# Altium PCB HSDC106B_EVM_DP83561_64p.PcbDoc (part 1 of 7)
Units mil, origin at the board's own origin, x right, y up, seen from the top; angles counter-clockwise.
Board outline 8750.24 x 6394.7 mil, 6 copper layers (Top Layer, GND1, SIG1, SIG2, GND2, Bottom Layer), stack 60.4 mil thick; 472 components, 324 nets, 1622 pads, 1086 vias.
Unrouted connection lines stored in the file: 1.
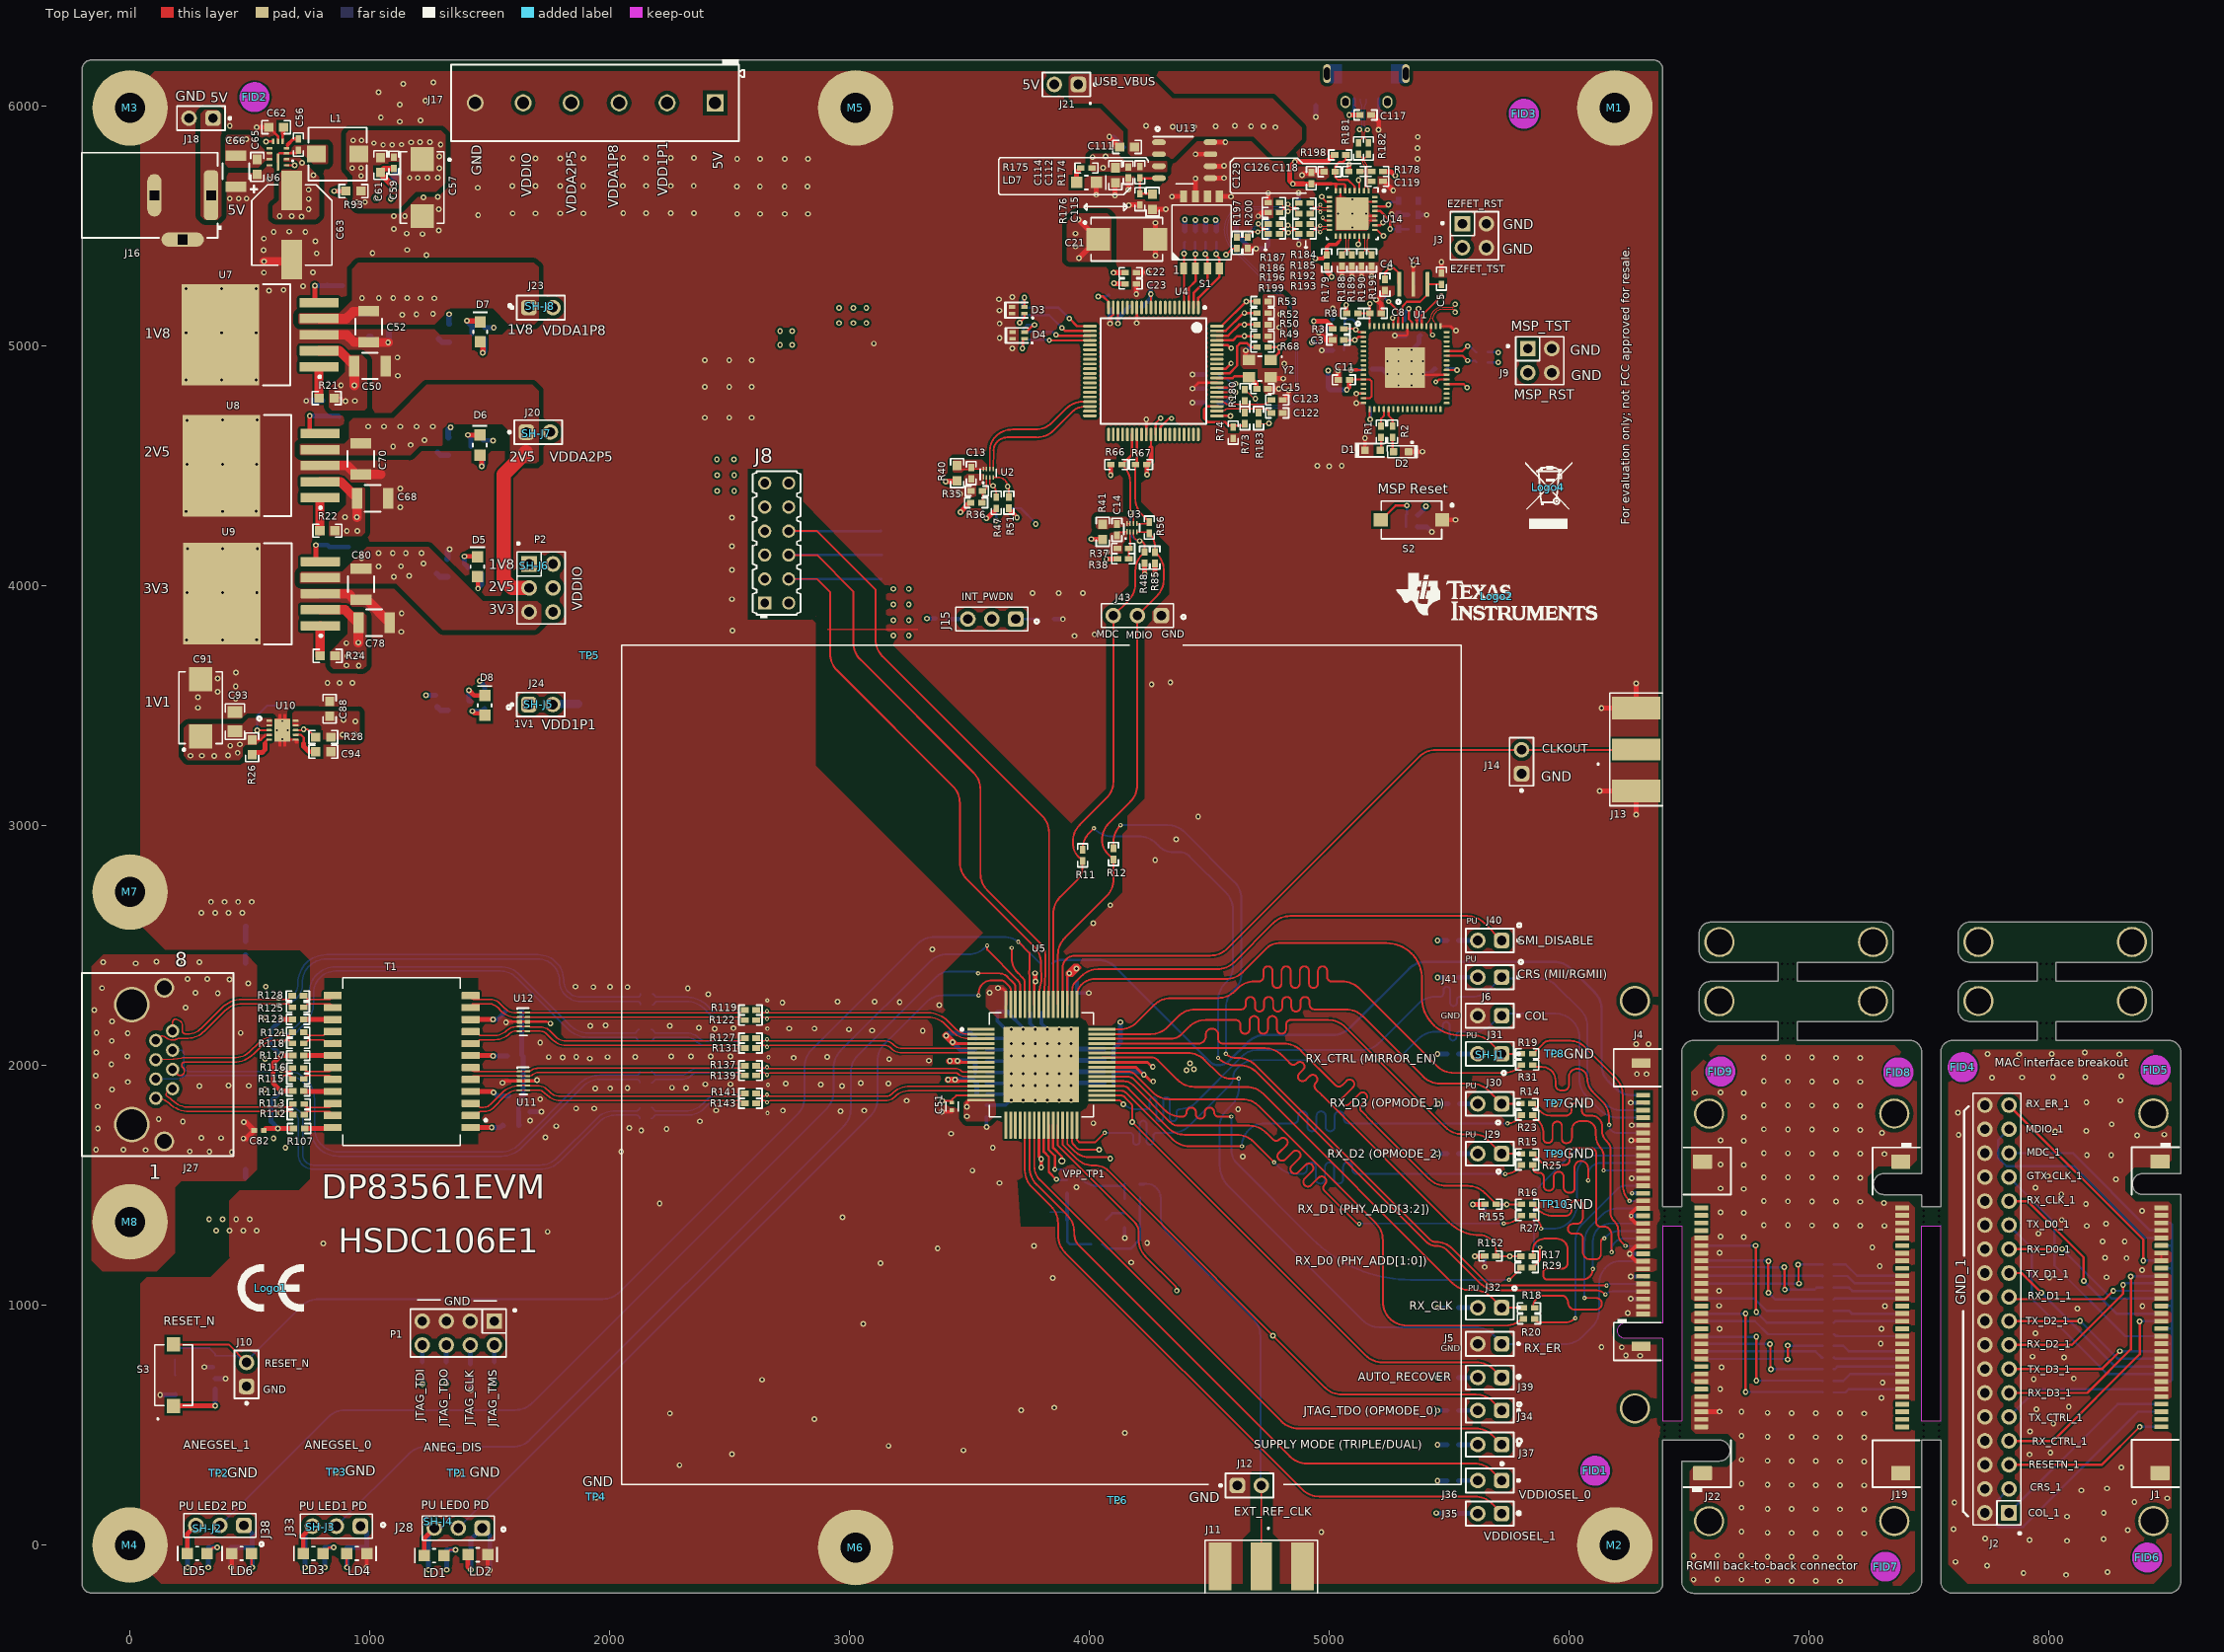
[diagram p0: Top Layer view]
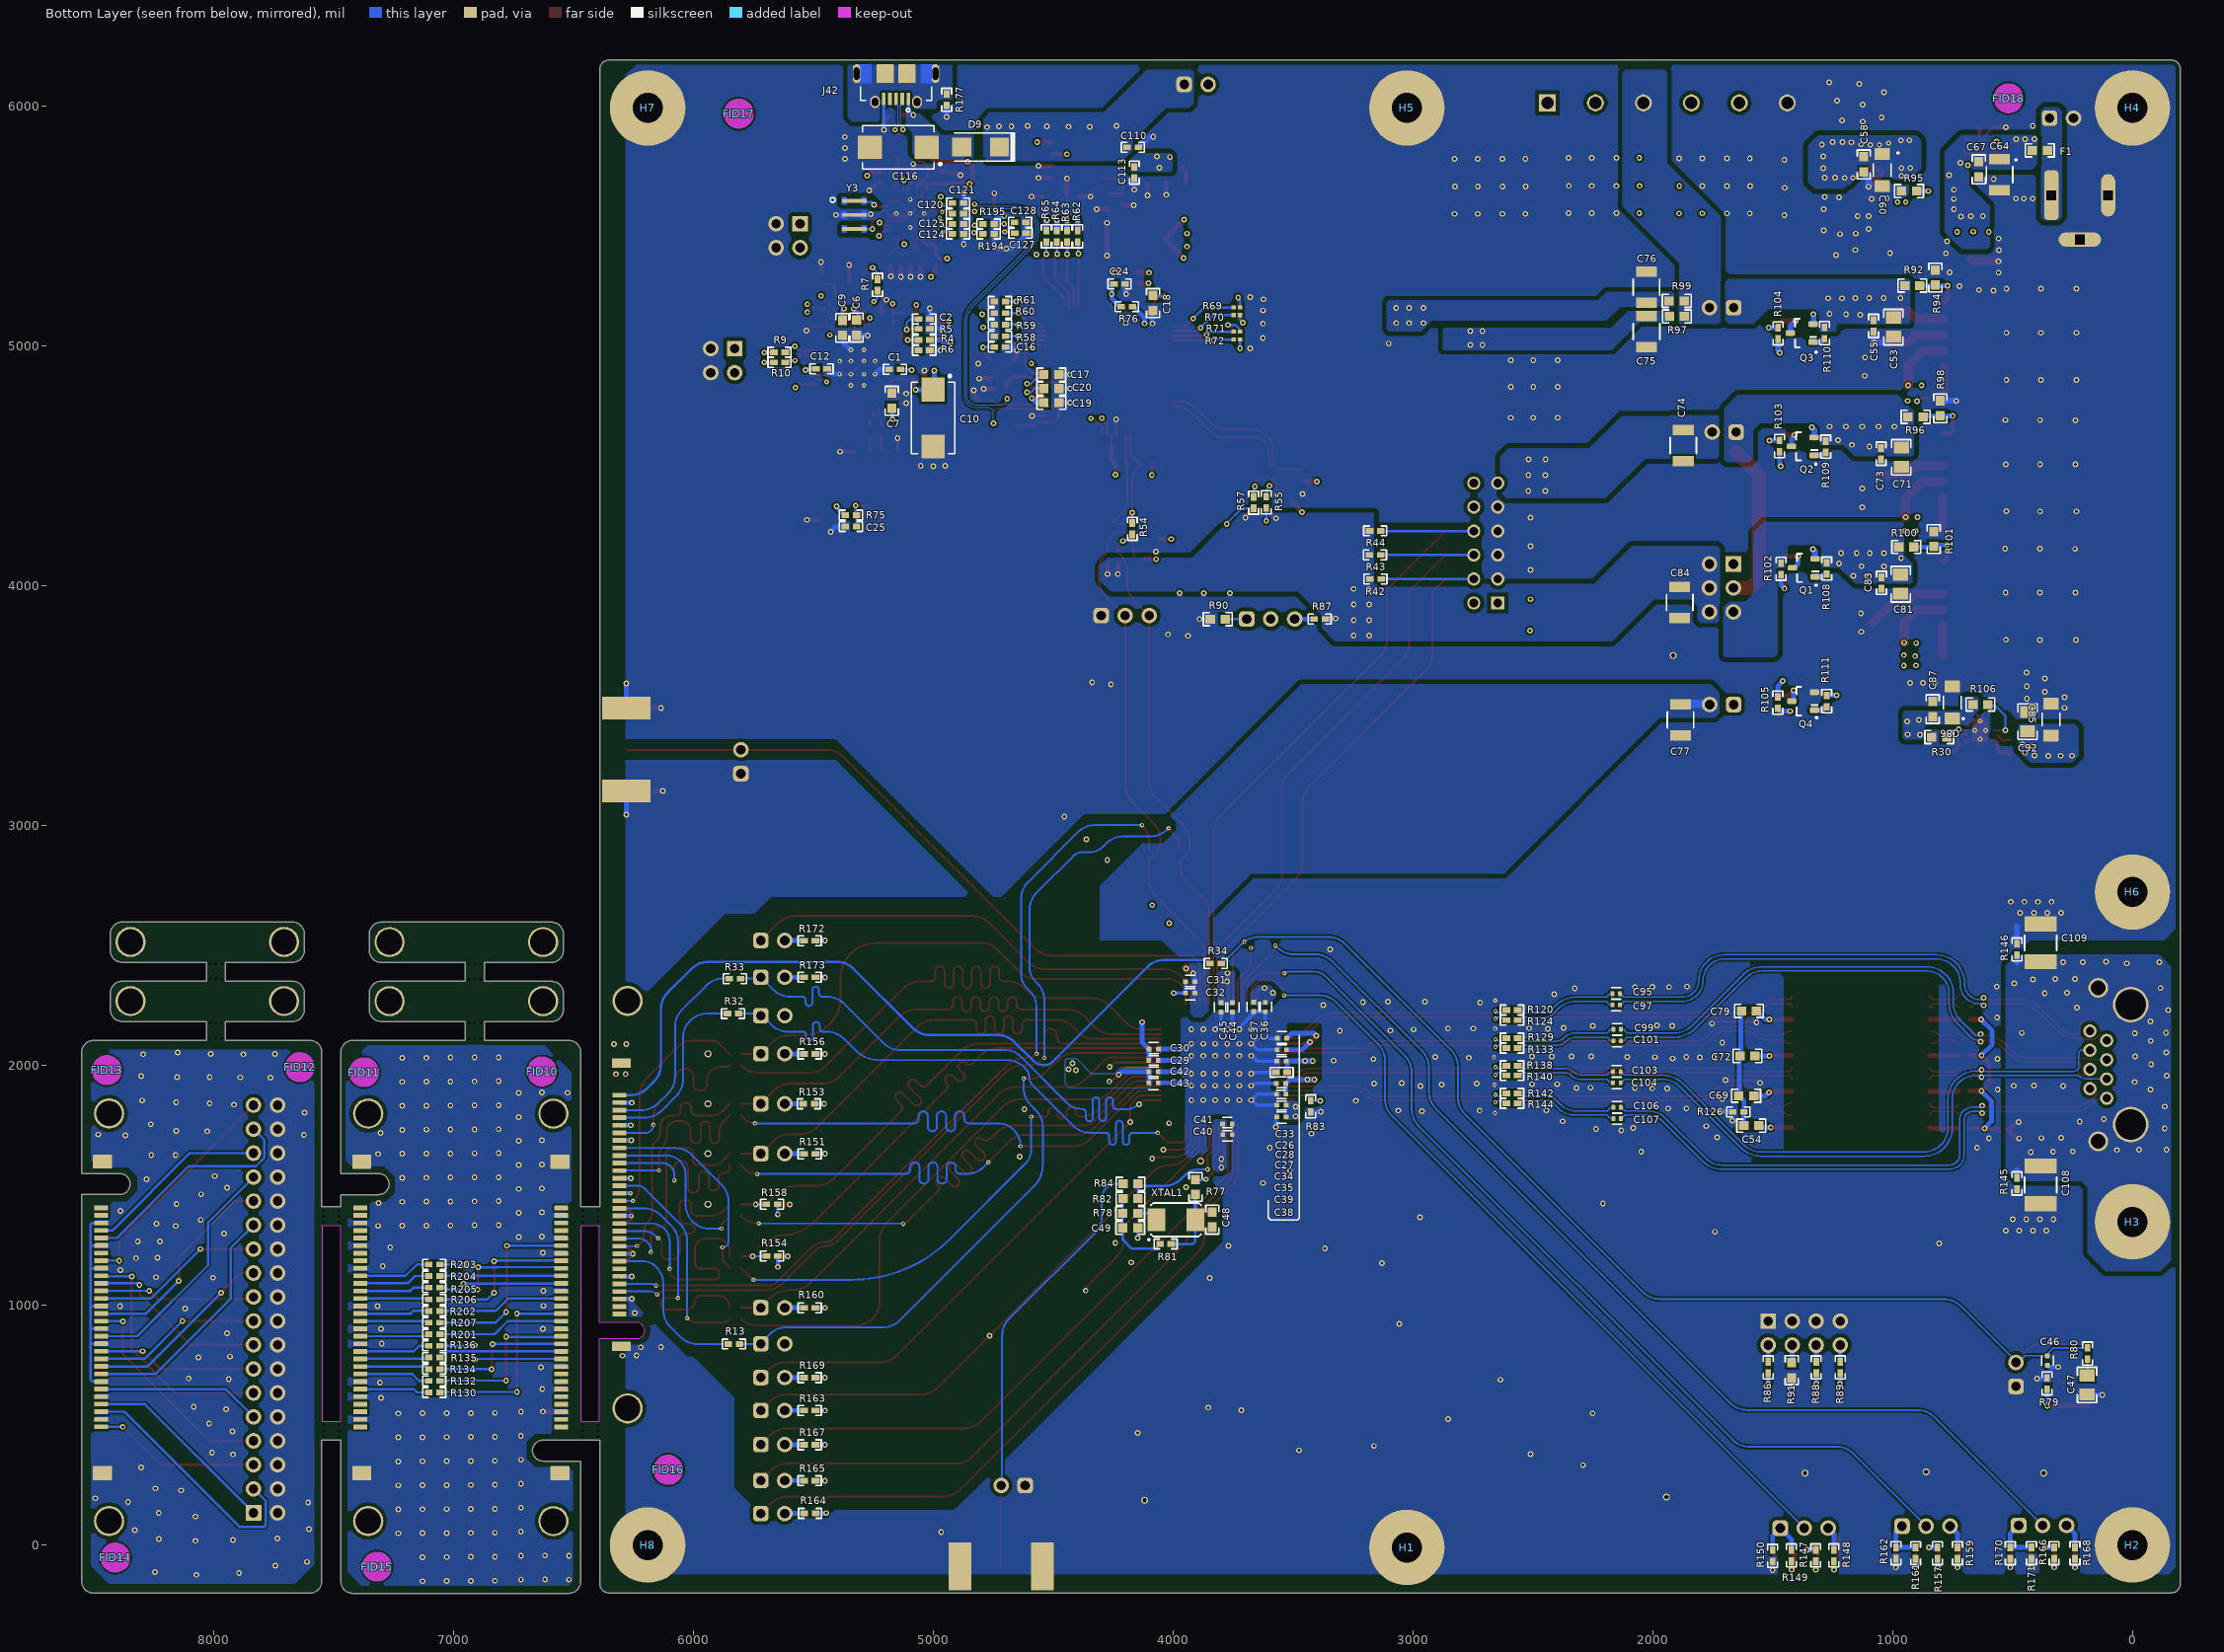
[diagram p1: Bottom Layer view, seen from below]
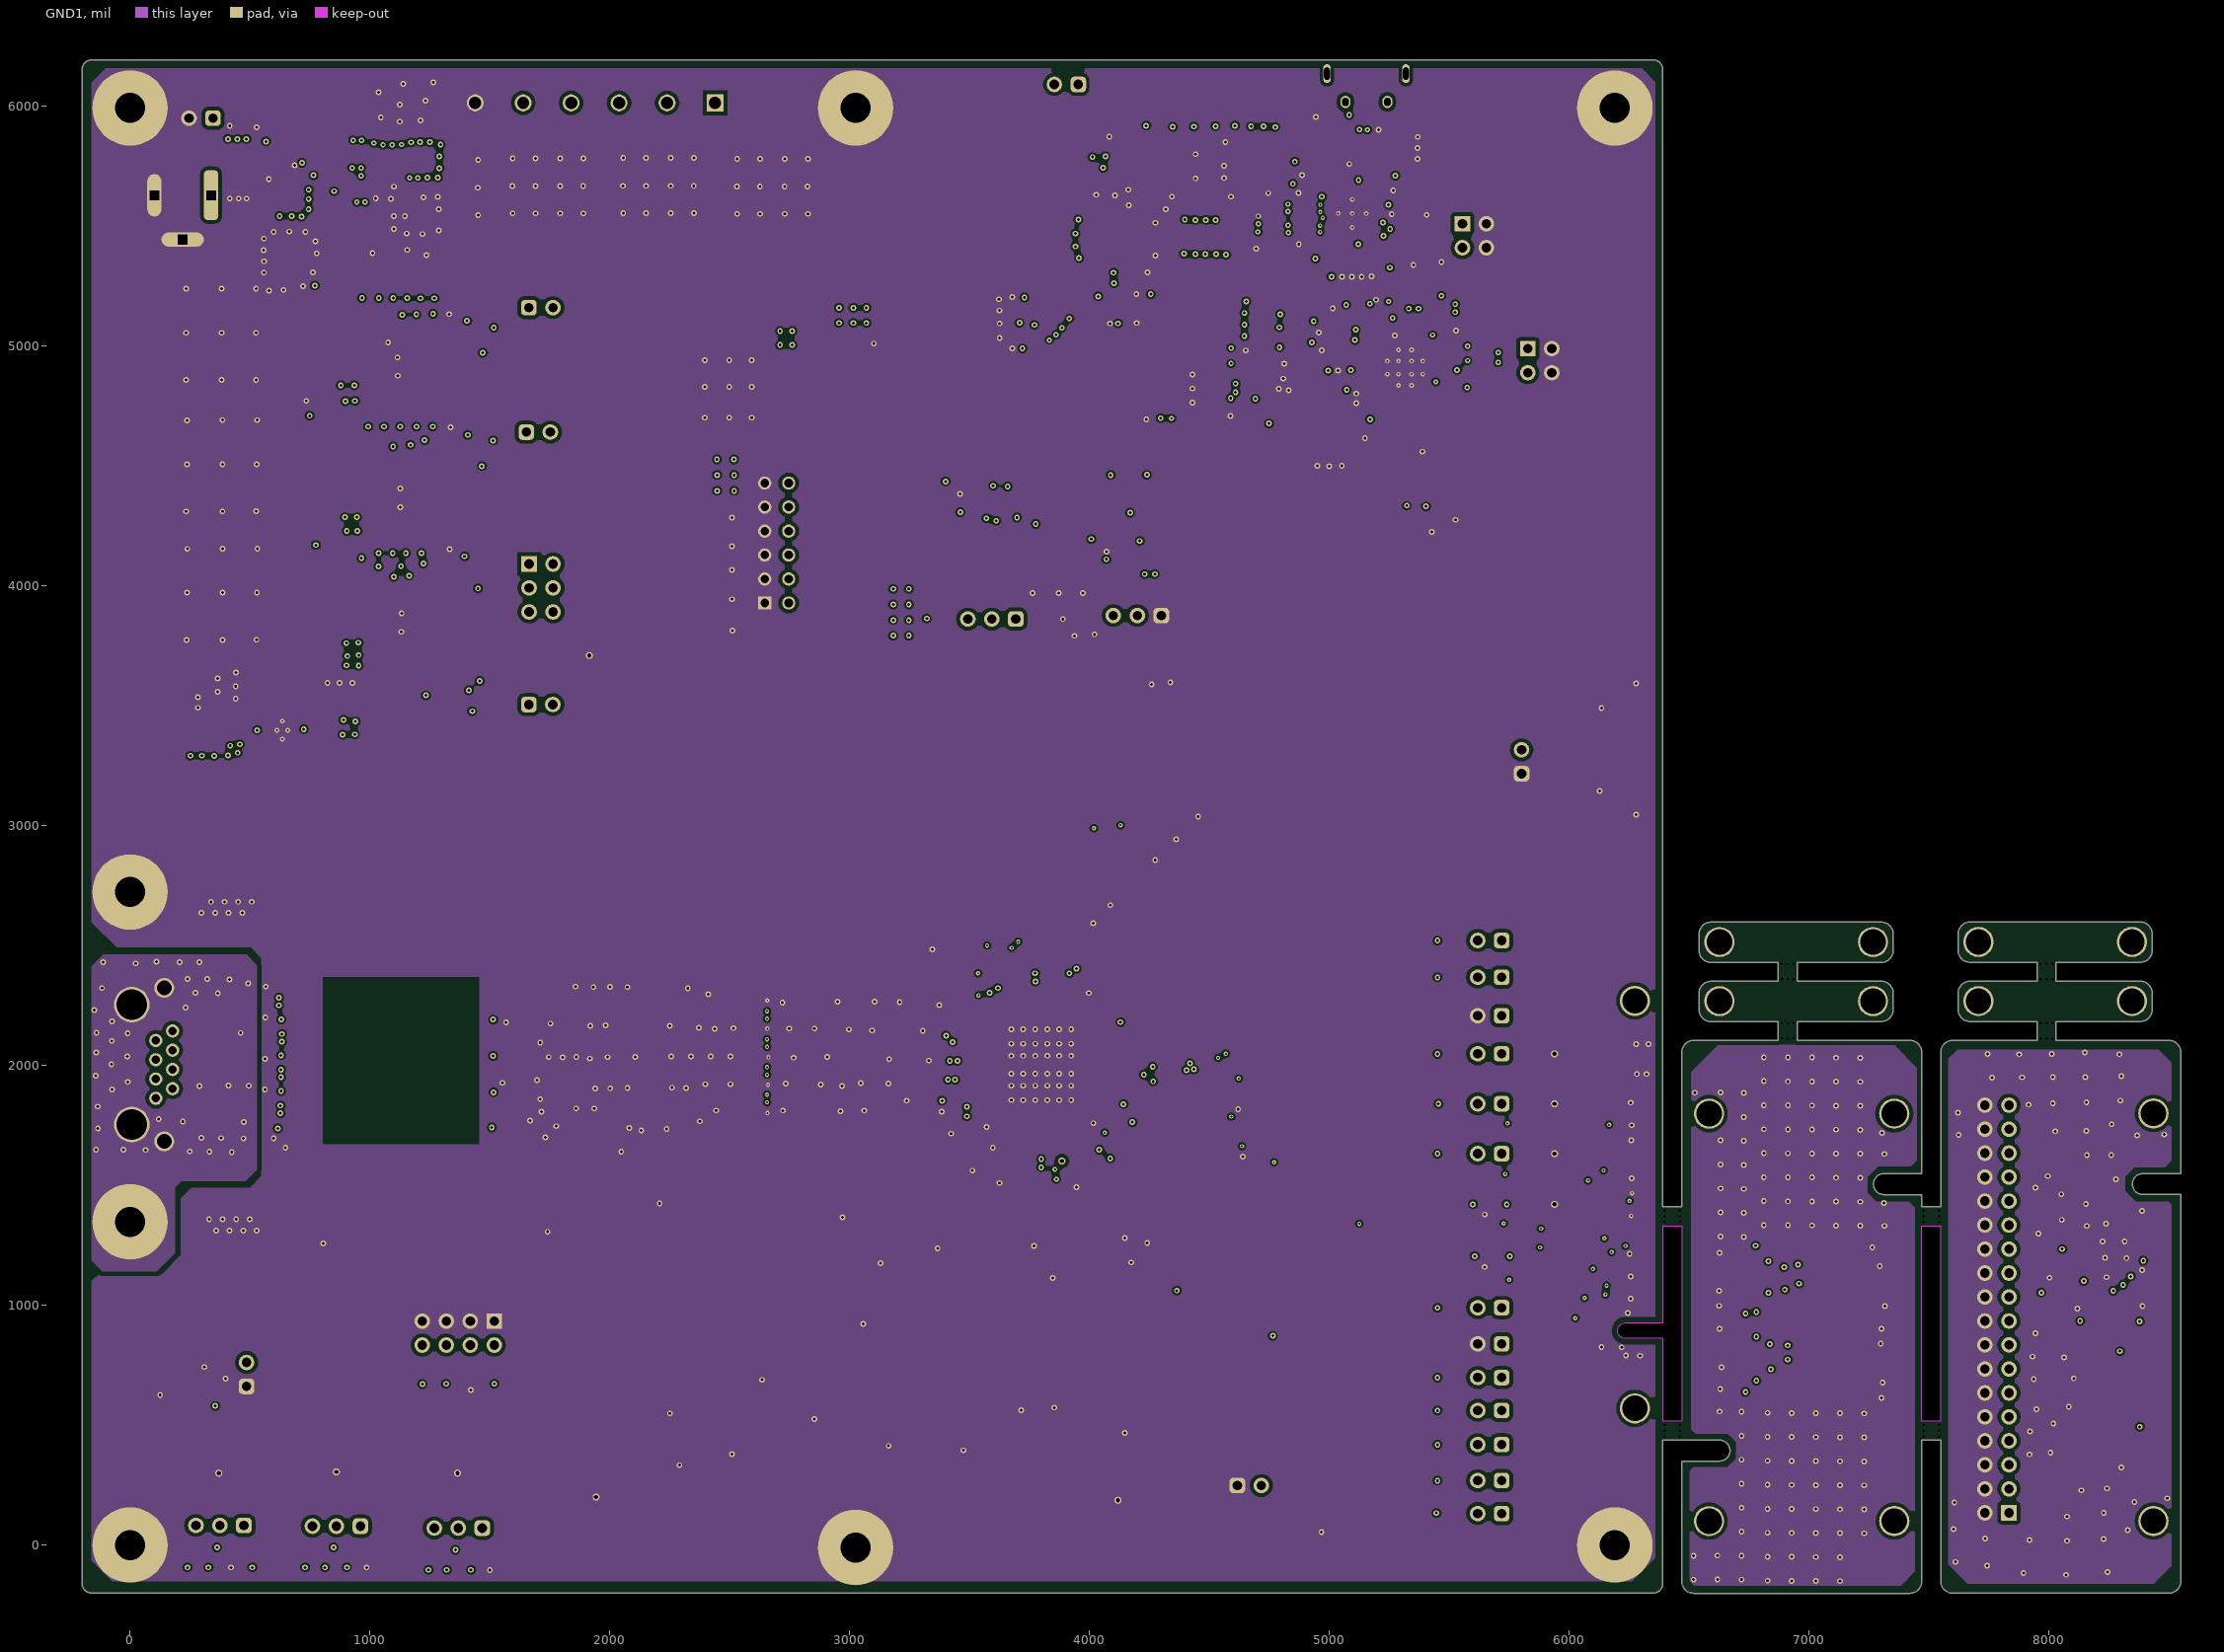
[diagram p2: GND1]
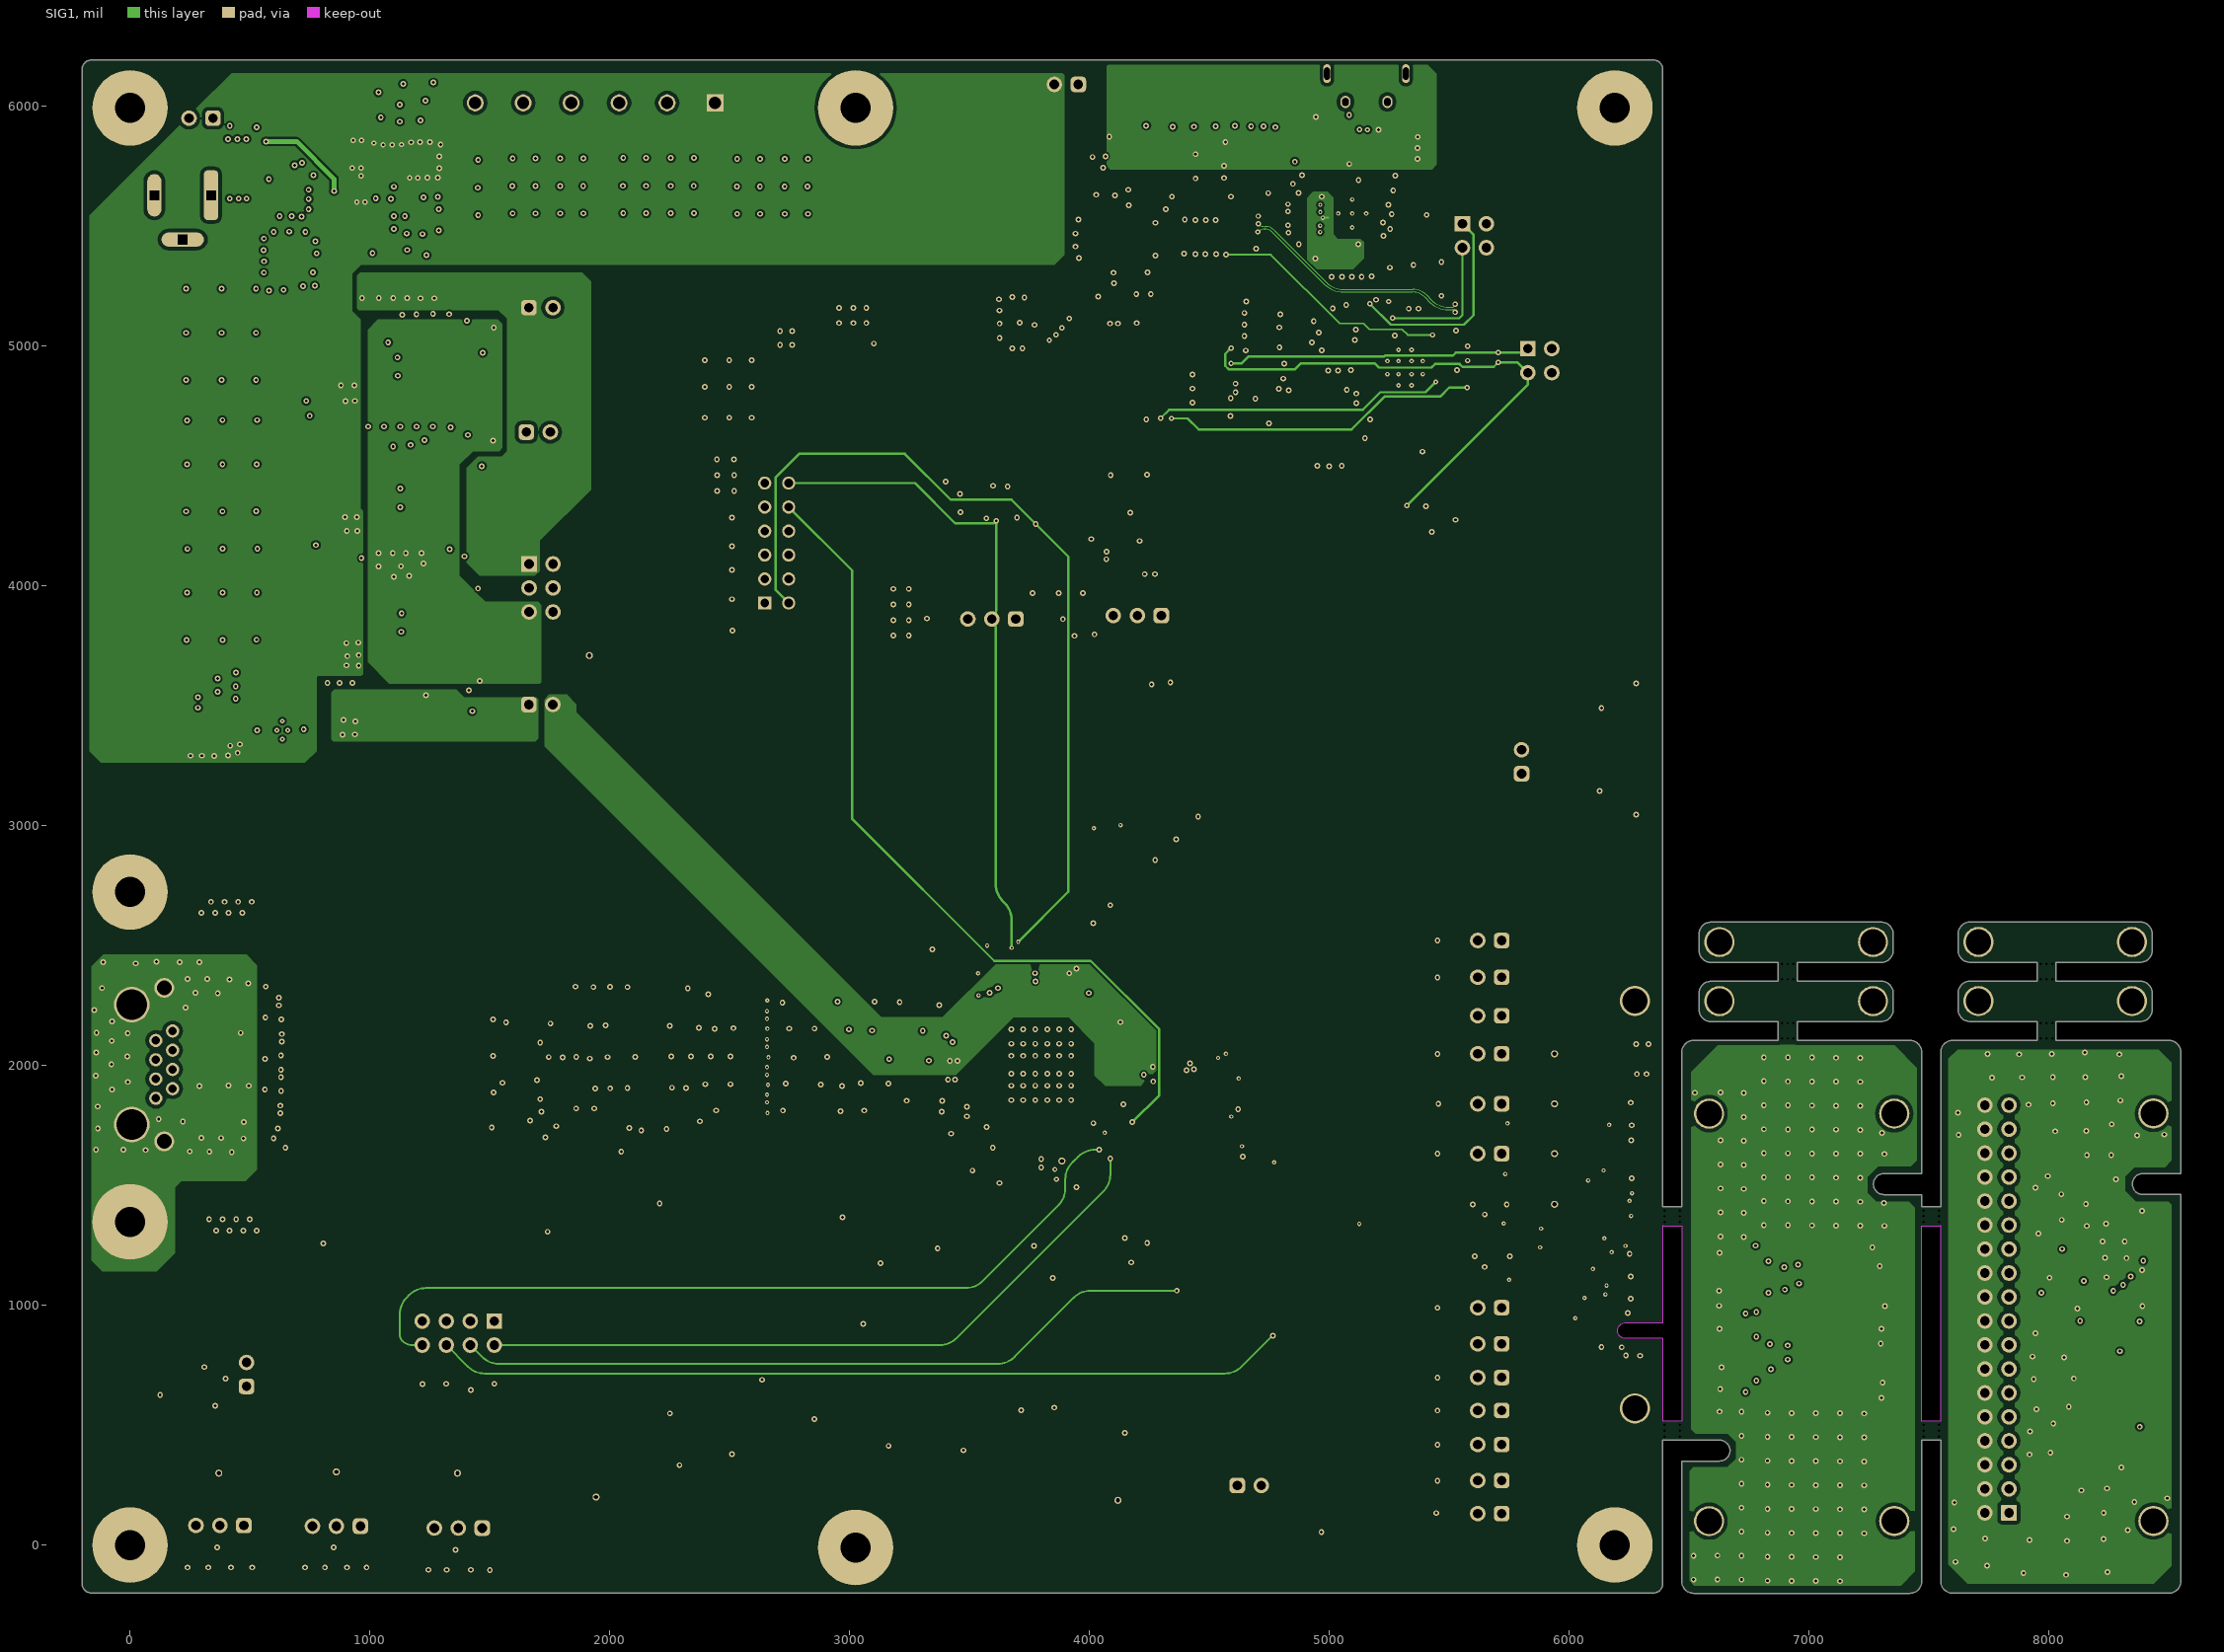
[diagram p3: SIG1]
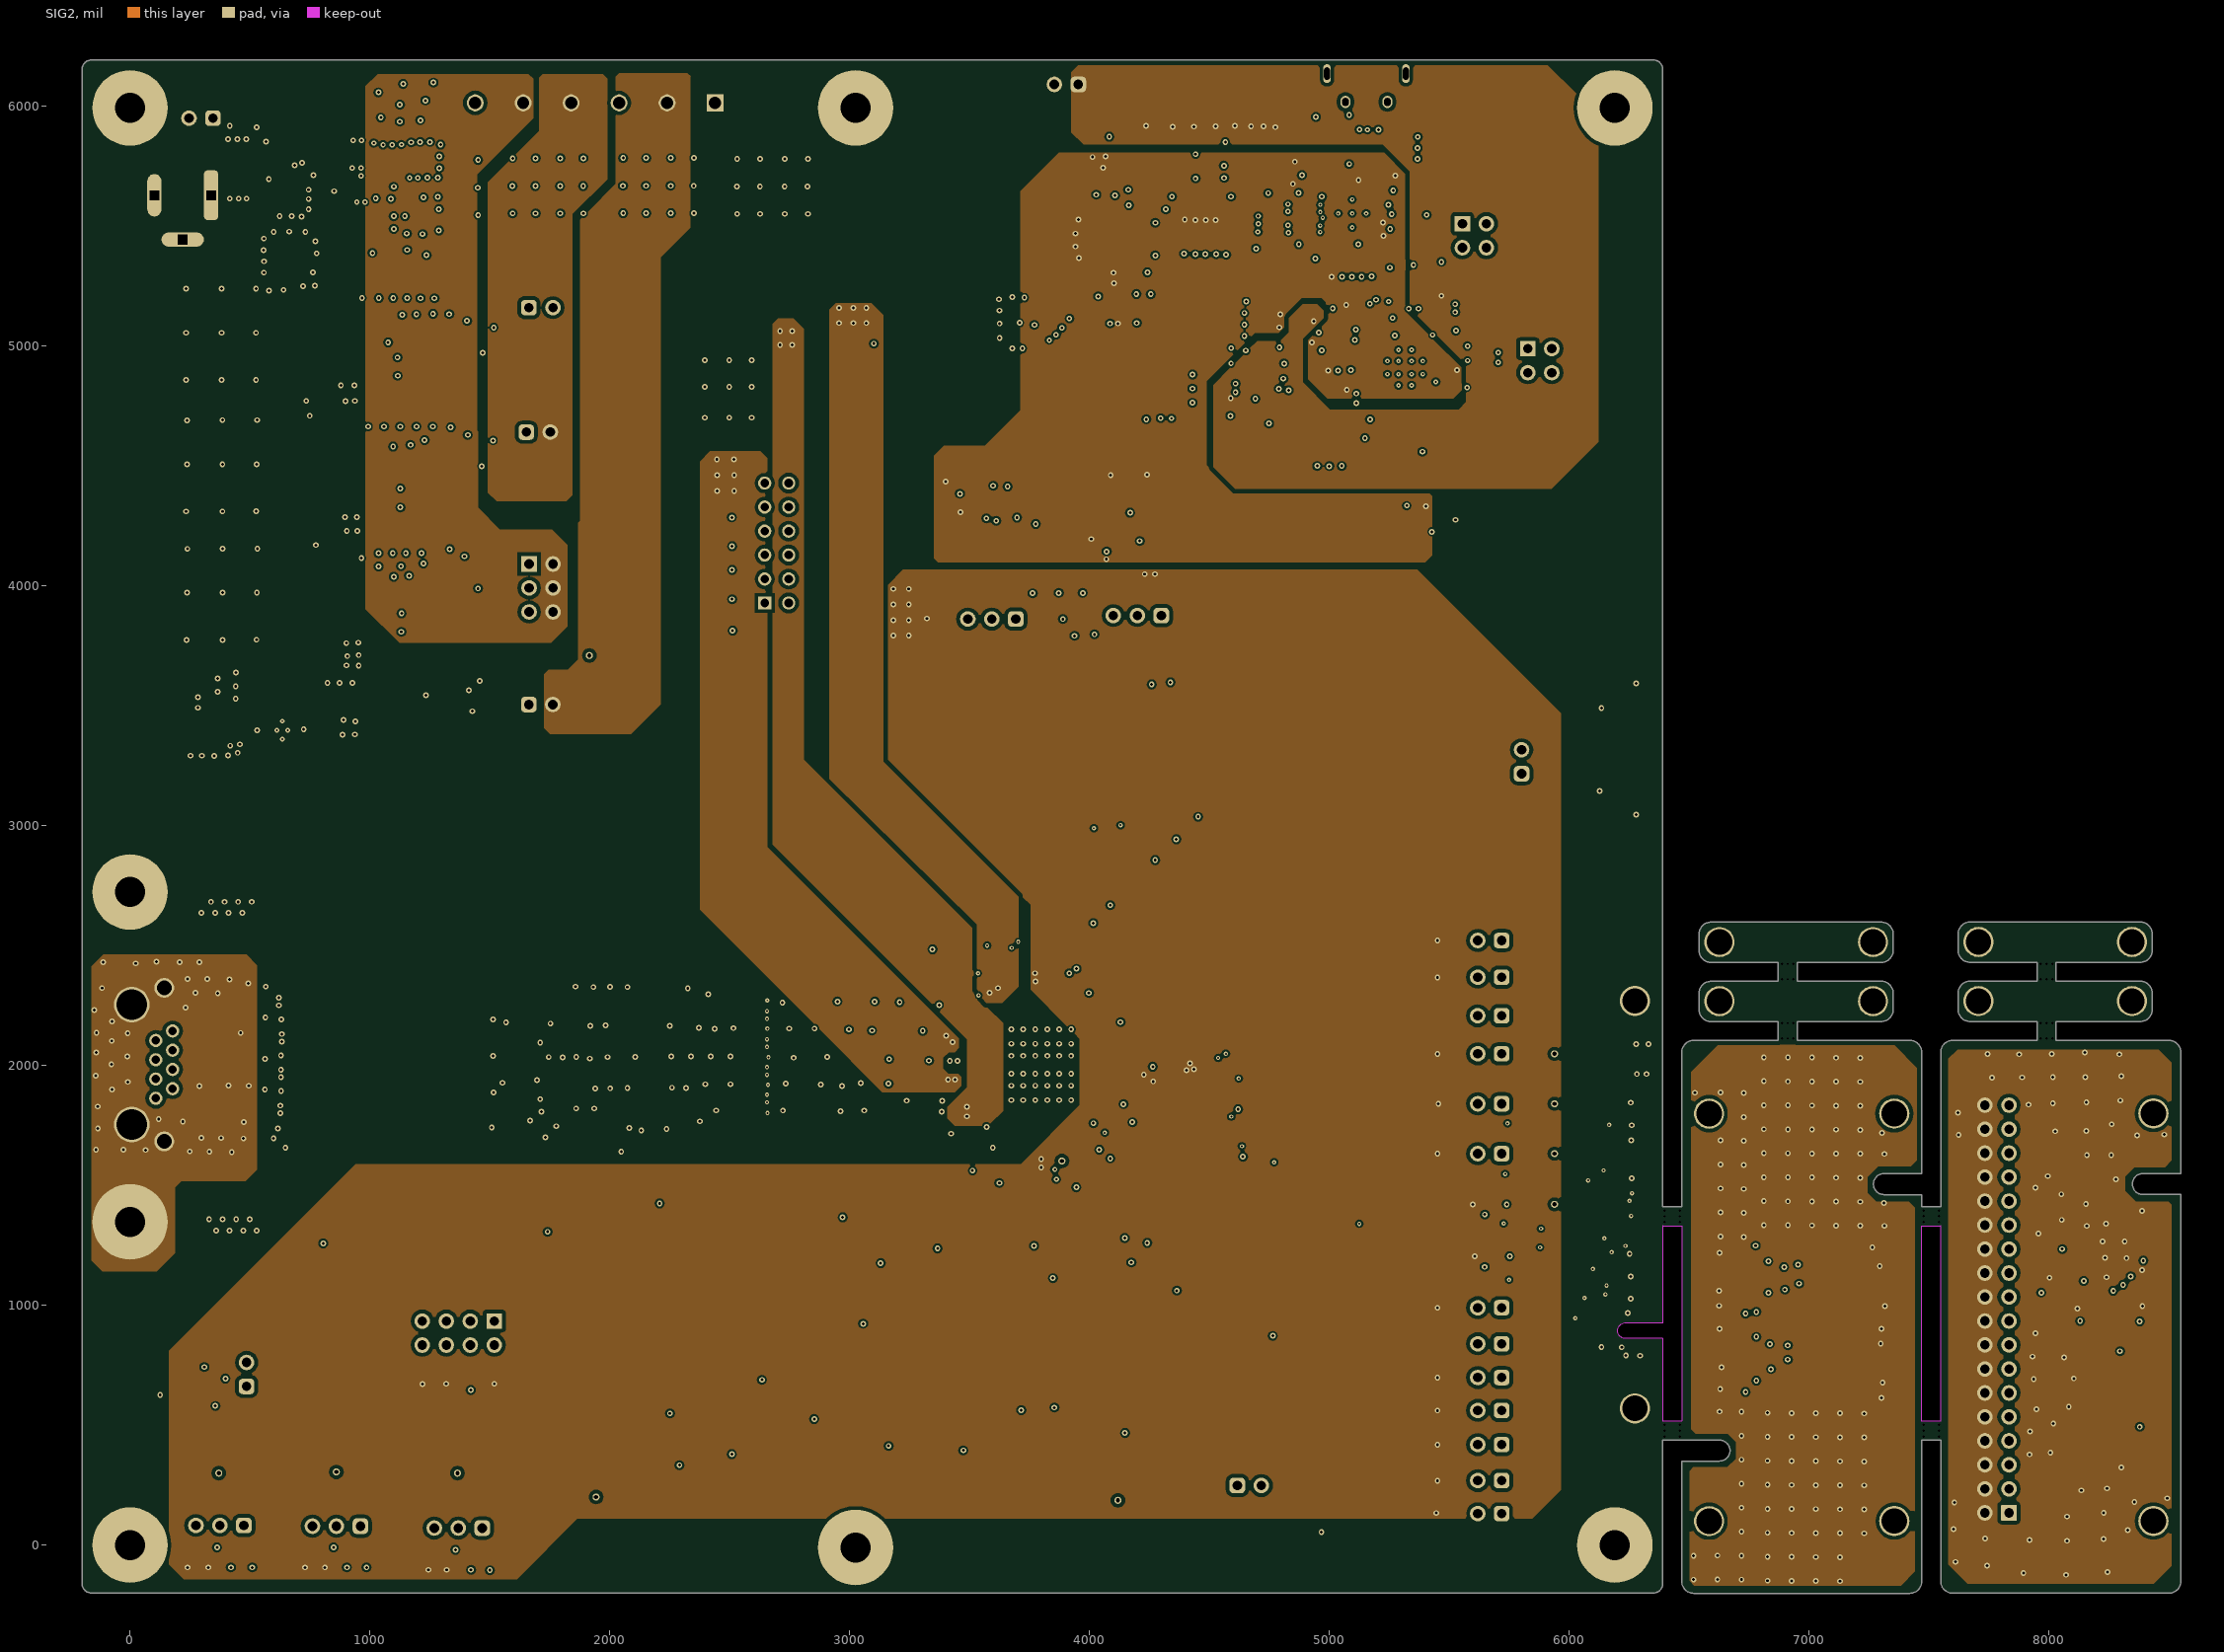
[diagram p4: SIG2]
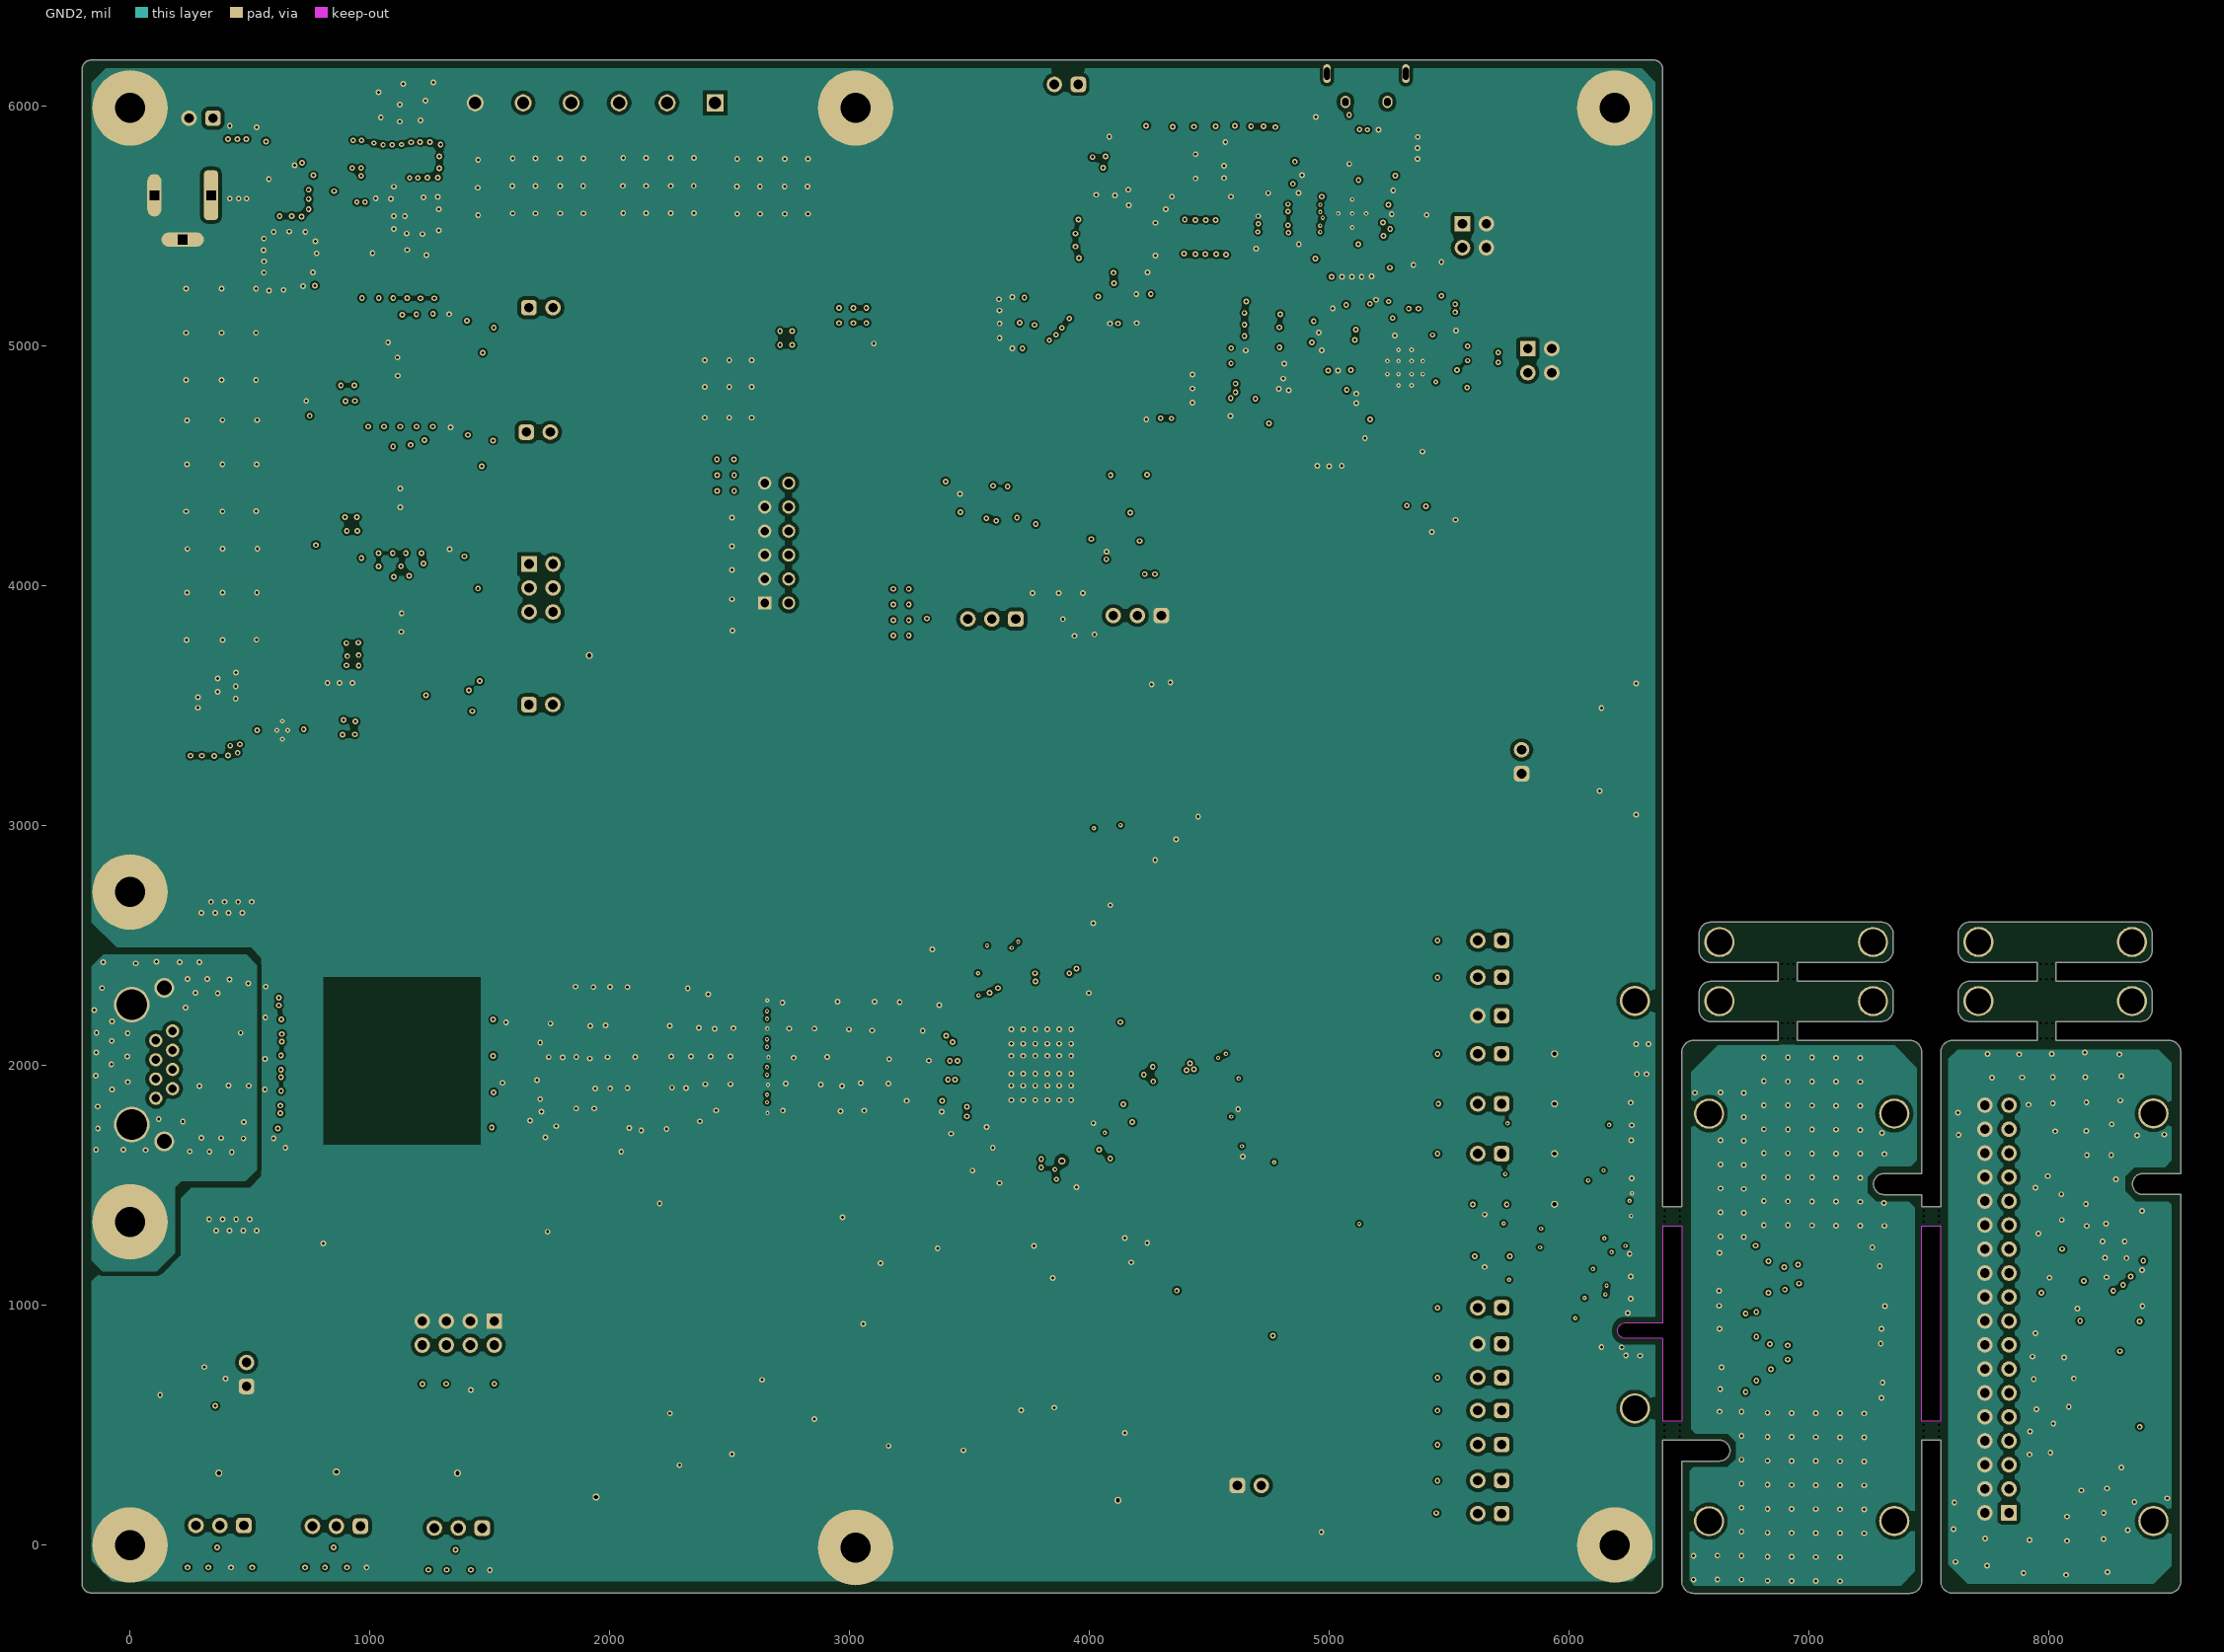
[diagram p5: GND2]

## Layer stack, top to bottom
Top Solder: solder mask 0.7, Solder Resist, Dk 3.5
Top Layer: signal copper 1.4
Dielectric 1: prepreg 5, FR-4 High Tg, Dk 4.6
GND1: signal copper 1.4
Dielectric  2: core 5, FR-4 High Tg, Dk 4.6
SIG1: signal copper 1.4
Dielectric 3: prepreg 32, FR-4 High Tg, Dk 4.6
SIG2: signal copper 1.4
Dielectric 4: core 5, FR-4 High Tg, Dk 4.6
GND2: signal copper 1.4
Dielectric 5: prepreg 5, FR-4 High Tg, Dk 4.6
Bottom Layer: signal copper 1.4
Bottom Solder: solder mask 0.7, Solder Resist, Dk 3.5

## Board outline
6350.55,-200 ccw(c6350.55,-160) 6390.55,-160 6390.55,437.61 6391.84,437.8 6627.15,437.8 cw(c6627.15,394.35) 6670.6,394.35 6670.6,393.93 cw(c6627.06,393.93) 6627.06,350.39 6469.58,350.39 6469.29,297.49 6469.29,-151 ccw(c6519.29,-151) 6519.29,-201 7420.39,-201 ccw(c7420.39,-151) 7470.39,-151 7470.39,438.1 7549.42,438.1 7549.42,350.7 7549.13,297.8 7549.13,-150.69 ccw(c7599.13,-150.69) 7599.13,-200.69 8500.24,-200.69 ccw(c8500.24,-150.69) 8550.24,-150.69 8550.24,1462.03 8391.97,1462.03 cw(c8391.97,1505.48) 8348.52,1505.48 8348.52,1505.89 cw(c8392.06,1505.89) 8392.06,1549.43 8550.24,1549.43 8550.24,2054.91 ccw(c8500.24,2054.91) 8500.24,2104.91 8030.39,2104.91 8030.39,2183.65 8380.97,2183.65 8380.97,2183.78 ccw(c8380.97,2233.78) 8430.97,2233.78 8430.97,2301.78 ccw(c8380.97,2301.78) 8380.97,2351.78 8380.84,2351.65 8030.39,2351.65 8030.39,2430.39 8380.97,2430.39 8380.97,2430.52 ccw(c8380.97,2480.52) 8430.97,2480.52 8430.97,2548.52 ccw(c8380.97,2548.52) 8380.97,2598.52 8380.84,2598.39 7671.68,2598.39 ccw(c7671.68,2548.39) 7621.68,2548.39 7621.68,2480.39 ccw(c7671.68,2480.39) 7671.68,2430.39 7951.65,2430.39 7951.65,2351.65 7671.68,2351.65 ccw(c7671.68,2301.65) 7621.68,2301.65 7621.68,2233.65 ccw(c7671.68,2233.65) 7671.68,2183.65 7951.65,2183.65 7951.65,2104.91 7599.13,2104.91 ccw(c7599.13,2054.91) 7549.13,2054.91 7549.13,1410.74 7470.39,1410.74 7470.39,1461.72 7312.13,1461.72 cw(c7312.13,1505.17) 7268.68,1505.17 7268.68,1505.59 cw(c7312.22,1505.59) 7312.22,1549.13 7470.39,1549.13 7470.39,2054.61 ccw(c7420.39,2054.61) 7420.39,2104.61 6950.55,2104.61 6950.55,2183.35 7301.13,2183.35 7301.13,2183.47 ccw(c7301.13,2233.47) 7351.13,2233.47 7351.13,2301.47 ccw(c7301.13,2301.47) 7301.13,2351.47 7301,2351.35 6950.55,2351.35 6950.55,2430.09 7301.13,2430.09 7301.13,2430.21 ccw(c7301.13,2480.21) 7351.13,2480.21 7351.13,2548.21 ccw(c7301.13,2548.21) 7301.13,2598.21 7301,2598.09 6591.84,2598.09 ccw(c6591.84,2548.09) 6541.84,2548.09 6541.84,2480.09 ccw(c6591.84,2480.09) 6591.84,2430.09 6871.81,2430.09 6871.81,2351.35 6591.84,2351.35 ccw(c6591.84,2301.35) 6541.84,2301.35 6541.84,2233.35 ccw(c6591.84,2233.35) 6591.84,2183.35 6871.81,2183.35 6871.81,2104.61 6519.29,2104.61 ccw(c6519.29,2054.61) 6469.29,2054.61 6469.29,1410.43 6390.55,1410.43 6390.55,6153.7 ccw(c6350.55,6153.7) 6350.55,6193.7 -160,6193.7 ccw(c-160,6153.7) -200,6153.7 -200,-160 ccw(c-160,-160) -160,-200
cut-out: 6390.55,1331.61 6390.64,1331.69 6469.29,1331.69 6469.29,517.25 6468.58,516.54 6390.84,516.54 6390.84,860.66 6390.55,860.95 6234.88,860.95 cw(c6234.88,893.32) 6202.5,893.32 6202.5,894.36 cw(c6236.01,894.36) 6236.01,927.88 6390.55,927.88 6390.55,927.87 6390.84,928.16 6390.84,1331.69
cut-out: 7470.68,1332 7549.13,1332 7548.42,1331.29 7548.42,516.84 7470.68,516.84

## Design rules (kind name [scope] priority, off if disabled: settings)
AcuteAngle [All] p1: minimum=4.50000000000000E+0001 checktracksonly=FALSE
AssemblyTestPointUsage [All] p1: valid=2
BoardOutlineClearance "j11 AND J13" [InComponent('J11')OR InComponent('J13')or InComponent('J42')or InComponent('J4') or InComponent('FID10')] p1: gap=0 ignorepadtopadclearanceinfootprint=FALSE except(25: Fill-OutlineEdge Poly-OutlineEdge Poly-CavityEdge Poly-CutoutEdge Poly-SplitBarrior Poly-SplitContinuation)
BoardOutlineClearance BoardOutlineClearance_MountingHoles [InComponentClass('Mounting_hole')] p2: gap=40 ignorepadtopadclearanceinfootprint=FALSE
BoardOutlineClearance BoardOutlineClearance_Poly [OnCopper or IsPoly] p3: gap=25 ignorepadtopadclearanceinfootprint=FALSE except(0: Arc-OutlineEdge Arc-CutoutEdge Track-OutlineEdge Track-CutoutEdge SMDPad-CutoutEdge THPad-OutlineEdge THPad-CutoutEdge Via-OutlineEdge Via-CutoutEdge Fill-CutoutEdge Region-CutoutEdge Text-OutlineEdge Text-CutoutEdge; 20: SMDPad-OutlineEdge Poly-OutlineEdge)
BoardOutlineClearance [OnCopper and Not InComponentClass('Logo') and not InComponentClass('FiducialMark') and not InRegion(1000,500,4000,800)] p4: gap=25 ignorepadtopadclearanceinfootprint=FALSE except(0: SMDPad-CutoutEdge THPad-CutoutEdge)
Clearance 100 [InDifferentialPairClass('100 Ohm') OR InDifferentialPairClass('USB')OR InDifferentialPairClass('DP0') vs InPolygon] p1: gap=18 ignorepadtopadclearanceinfootprint=FALSE
Clearance U2/3 [IsTrack or IsPad or IsArc vs IsTrack or IsPad or IsArc] p2: gap=7.48 ignorepadtopadclearanceinfootprint=FALSE except(0: Arc-SMDPad; 4.6: Arc-Arc Arc-Track Arc-Via Track-Track Track-SMDPad Track-Via)
Clearance "Clearance_RooM U7" [WithinRoom('Room U7')] p3: gap=5.9 ignorepadtopadclearanceinfootprint=FALSE except(8: Arc-Fill Arc-Poly Arc-Region Track-Fill Track-Poly Track-Region SMDPad-Fill SMDPad-Poly SMDPad-Region THPad-Fill THPad-Poly THPad-Region Via-Fill Via-Poly Via-Region Fill-Fill Fill-Poly Fill-Region Poly-Poly Poly-Region Region-Region)
Clearance Gnd_MDI [InNetClass('TD_x_gnd') vs InNet('GND') or InNet('RJ45_ERTH')] p4: gap=18 ignorepadtopadclearanceinfootprint=FALSE except(5: SMDPad-SMDPad; 8: Arc-Arc Arc-Track Arc-SMDPad Arc-THPad Arc-Via Track-Track Track-SMDPad Track-THPad Track-Via; 15: SMDPad-Via)
Clearance "50 OHM" [InNetClass('50 OHM') vs InNet('GND') or InNet('RJ45_ERTH')] p5: gap=8 ignorepadtopadclearanceinfootprint=FALSE except(5: SMDPad-SMDPad; 7.78: SMDPad-Fill SMDPad-Poly SMDPad-Region; 7.87: Arc-Via Track-Via Via-Fill Via-Poly Via-Region; 15: SMDPad-Via; 18: SMDPad-THPad THPad-THPad THPad-Via THPad-Fill THPad-Poly THPad-Region Fill-Fill Fill-Poly Fill-Region Poly-Poly Poly-Region Region-Region; 20: Arc-Fill Arc-Poly Arc-Region Track-Fill Track-Poly Track-Region)
Clearance Clearance_Poly [InPolygon] p6: gap=8 ignorepadtopadclearanceinfootprint=FALSE except(0: Arc-Hole Track-Hole SMDPad-Hole THPad-Hole Via-Hole Fill-Hole Poly-Hole Region-Hole Text-Hole; 10: SMDPad-Poly; 15: THPad-Poly Fill-Poly; 20: Poly-Poly)
Clearance J10_Pad [InPadClass('J10')] p7: gap=7.87 ignorepadtopadclearanceinfootprint=FALSE except(10: Arc-Poly Track-Poly SMDPad-Poly THPad-Poly Via-Poly Fill-Poly Poly-Poly)
Clearance keepout_Pad [IsKeepOut vs InComponentClass('Edge_connector')] p8: gap=0 ignorepadtopadclearanceinfootprint=TRUE
Clearance Mounting_hole [InPadClass('MH')] p9: gap=40 ignorepadtopadclearanceinfootprint=TRUE
Clearance Clearance_FiducialMark [InComponentClass('Fiducial')] p10: gap=20 ignorepadtopadclearanceinfootprint=FALSE
Clearance Clearance_1 [isvia vs inpoly] p11: gap=8 ignorepadtopadclearanceinfootprint=TRUE
Clearance Clearance_Keepouts [((IsTrack Or IsArc) And Not InPoly) And IsFree and IsKeepOut vs ((IsTrack Or IsArc) And Not InPoly) And IsFree and IsKeepOut] p12: gap=0 ignorepadtopadclearanceinfootprint=FALSE
Clearance [All] p13: gap=7.87 ignorepadtopadclearanceinfootprint=TRUE except(0: Arc-SMDPad Arc-Hole Track-Hole SMDPad-Hole THPad-Hole Via-Hole Fill-Hole Poly-Hole Region-Hole Text-Hole; 4.6: Arc-Track Arc-Via Track-Track Track-SMDPad Track-Via; 7.6: SMDPad-SMDPad; 15: Poly-Region; 20: Arc-Poly Track-Poly Poly-Poly)
ComponentClearance ComponentClearance_jumper [All vs HasFootprint('Harwin_M7582-05')] p1: gap=0 collisioncheckmode=3 verticalgap=0 showdistances=FALSE
ComponentClearance J10_H1 [InComponentClass('SFP')or InComponent('J2') or InComponent('J4')or InComponent('J22')] p2: gap=0 collisioncheckmode=3 verticalgap=0 showdistances=FALSE
ComponentClearance ComponentClearance_Shunt [InComponentClass('Header') OR InComponent('J30') vs InComponentClass('Shunt')] p3: gap=0 collisioncheckmode=3 verticalgap=0 showdistances=FALSE
ComponentClearance ComponentClearance_Fiducial [InComponent('H1') vs InComponentClass('FiducialMark')] p4: gap=0 collisioncheckmode=3 verticalgap=0 showdistances=FALSE
ComponentClearance ComponentClearance_Fiber [InComponent('J3') vs InComponent('H1')] p5: gap=0 collisioncheckmode=3 verticalgap=0 showdistances=FALSE
ComponentClearance ComponentClearance_MountingHoles_FiducialMarks [InComponentClass('Mounting Holes') vs InComponentClass('FiducialMark')] p6: gap=50 collisioncheckmode=3 verticalgap=10 showdistances=FALSE
ComponentClearance ComponentClearance_Logo [InComponentClass('Logo')] p7: gap=50 collisioncheckmode=3 verticalgap=10 showdistances=FALSE
ComponentClearance ComponentClearance_ScrewToNut [(HasFootprint('NY PMS 440 0025 PH')) vs (HasFootprint('Keystone_1902C'))] p8: gap=5 collisioncheckmode=3 verticalgap=10 showdistances=FALSE
ComponentClearance ComponentClearance_MountingHoles [InComponentClass('Mounting Holes')] p9: gap=250 collisioncheckmode=3 verticalgap=100000 showdistances=FALSE
ComponentClearance ComponentClearance_SmallPassives [HasFootprint('0201*') or HasFootprint('0402*') or HasFootprint('0508') or HasFootprint('0603*') or HasFootprint('0612') or HasFootprint('0805*') or HasFootprint('0815*') or HasFootprint('0830*') or HasFootprint('1206*') or HasFootprint('1210*') or HasFootprint('1808*') or HasFootprint('1812*') or HasFootprint('1825*') or HasFootprint('2010*') or HasFootprint('2220*') or HasFootprint('2225*') or HasFootprint('2512*') or HasFootprint('2728*') or HasFootprint('3518*') vs HasFootprint('0201*') or HasFootprint('0402*') or HasFootprint('0508') or HasFootprint('0603*') or HasFootprint('0612') or HasFootprint('0805*') or HasFootprint('0815*') or HasFootprint('0830*') or HasFootprint('1206*') or HasFootprint('1210*') or HasFootprint('1808*') or HasFootprint('1812*') or HasFootprint('1825*') or HasFootprint('2010*') or HasFootprint('2220*') or HasFootprint('2225*') or HasFootprint('2512*') or HasFootprint('2728*') or HasFootprint('3518*')] p10: gap=10 collisioncheckmode=3 verticalgap=10 showdistances=FALSE
ComponentClearance ComponentClearance_THtoSMT [IsThruComponent vs IsSMTComponent] p11: gap=10 collisioncheckmode=3 verticalgap=10 showdistances=FALSE
ComponentClearance ComponentClearance_THtoTH [IsThruComponent vs IsThruComponent] p12: gap=30 collisioncheckmode=3 verticalgap=30 showdistances=FALSE
ComponentClearance [All] p13: gap=10 collisioncheckmode=3 verticalgap=10 showdistances=FALSE
DiffPairsRouting USB_1 [InDifferentialPairClass('USB')] p1: maxlimit=6.1 minlimit=4.6 mostfreqgap=6.1 toplayer_maxgap=4.6 toplayer_prefgap=4.6 toplayer_minwidth=5 toplayer_maxwidth=5 toplayer_prefwidth=5 midlayer1_mingap=6.1 midlayer1_minwidth=5 midlayer1_maxwidth=5 midlayer1_prefwidth=5 midlayer2_mingap=6.1 midlayer2_minwidth=5 midlayer2_maxwidth=5 midlayer2_prefwidth=5 midlayer3_mingap=6.1 midlayer3_minwidth=5 midlayer3_maxwidth=5 midlayer3_prefwidth=5 midlayer6_mingap=6.1 midlayer6_minwidth=5 midlayer6_maxwidth=5 midlayer6_prefwidth=5 bottomlayer_maxgap=4.6 bottomlayer_prefgap=4.6 bottomlayer_minwidth=5 bottomlayer_maxwidth=5 bottomlayer_prefwidth=5 maxuncoupledlength=1000
DiffPairsRouting "100 Ohm" [InDifferentialPairClass('100 Ohm')] p2: maxlimit=12 minlimit=11 mostfreqgap=12 toplayer_mingap=12 toplayer_minwidth=6 toplayer_maxwidth=6 toplayer_prefwidth=6 midlayer1_mingap=12 midlayer1_minwidth=6 midlayer1_maxwidth=6 midlayer1_prefwidth=6 midlayer2_maxgap=11 midlayer2_prefgap=11 midlayer2_minwidth=6 midlayer2_maxwidth=6 midlayer2_prefwidth=6 midlayer3_maxgap=11 midlayer3_prefgap=11 midlayer3_minwidth=6 midlayer3_maxwidth=6 midlayer3_prefwidth=6 midlayer6_mingap=12 midlayer6_minwidth=6 midlayer6_maxwidth=6 midlayer6_prefwidth=6 bottomlayer_mingap=12 bottomlayer_minwidth=6 bottomlayer_maxwidth=6 bottomlayer_prefwidth=6 maxuncoupledlength=500
FabricationTestPointUsage TestPointUsage [All] p1: valid=2 allowmultiple=FALSE
FabricationTestpoint Testpoint [All] p1: side=3 testpointundercomponent=TRUE minsize=40 maxsize=100 preferedsize=60 minholesize=0 maxholesize=40 preferedholesize=32 testpointgrid=1 allowsidetop=TRUE allowsidebottom=TRUE usegrid=TRUE gridtolerance=0.01
FanoutControl Fanout_LCC [IsLCC] p1: bgadir=Out bgaviamode=Centered fanoutstyle=Auto fanoutdirection=Alternating viagrid=1 // Fanout_LCC (Default Rule)
FanoutControl Fanout_BGA [IsBGA] p2: bgadir=Out bgaviamode=Centered fanoutstyle=Auto fanoutdirection=Alternating viagrid=1 // Fanout_BGA (Default Rule)
FanoutControl Fanout_Default [All] p4: bgadir=Out bgaviamode=Centered fanoutstyle=Auto fanoutdirection=Alternating viagrid=1 // Fanout_Default (Default Rule)
FanoutControl Fanout_Small [(CompPinCount < 5)] p5: bgadir=Out bgaviamode=Centered fanoutstyle=Auto fanoutdirection=OutThenIn viagrid=1 // Fanout_Small (Default Rule)
HoleSize [All] p1: absolutevalues=TRUE maxlimit=251 minlimit=7.87 maxpercent=80.000 minpercent=20.000
MatchedLengths TX_CS [InNetClass('TX_CS')] p1: tolerance=30 checknetsindiffpair=FALSE checkdiffpairvsdiffpair=TRUE checkxsignals=TRUE checkothers=TRUE
MatchedLengths TX_Break [InNetClass('TX_Break_out')] p2: tolerance=100 checknetsindiffpair=FALSE checkdiffpairvsdiffpair=TRUE checkxsignals=TRUE checkothers=TRUE
MatchedLengths RX_Break [InNetClass('RX_Break_out')] p3: tolerance=100 checknetsindiffpair=FALSE checkdiffpairvsdiffpair=TRUE checkxsignals=TRUE checkothers=TRUE
MatchedLengths TX [InNetClass('TX_SIGNAL')] p4: tolerance=10 checknetsindiffpair=FALSE checkdiffpairvsdiffpair=TRUE checkxsignals=TRUE checkothers=TRUE
MatchedLengths RX [InNetClass('RX_SIGNAL')] p5: tolerance=10 checknetsindiffpair=FALSE checkdiffpairvsdiffpair=TRUE checkxsignals=TRUE checkothers=TRUE
MatchedLengths MatchedLengths_RGMIITX [InNetClass('RGMII_TX')] p6: tolerance=150 checknetsindiffpair=FALSE checkdiffpairvsdiffpair=TRUE checkxsignals=TRUE checkothers=TRUE
MatchedLengths MatchedLengths_RGMIIRX [InNetClass('RGMII_RX')] p7: tolerance=200 checknetsindiffpair=FALSE checkdiffpairvsdiffpair=TRUE checkxsignals=TRUE checkothers=TRUE
MinimumAnnularRing MinimumAnnularRing_ThermalPadVias [IsVia and InAnyComponent] p1: minimumring=5
MinimumAnnularRing [All] p2: minimumring=3.94
MinimumSolderMaskSliver MinimumSolderMaskSliver_Logo [InComponentClass('Logo') vs InComponentClass('Logo')] p1: minsoldermaskwidth=0.7
MinimumSolderMaskSliver [All] p2: minsoldermaskwidth=3.94
PlaneClearance [All] p1: clearance=8
PlaneConnect "Thermal relif_1" [InComponentClass('Thermal relif')] p1: planeconnectstyle=Relief reliefexpansion=20 reliefentries=4 reliefconductorwidth=15 reliefairgap=10
PlaneConnect [All] p2: planeconnectstyle=Relief reliefexpansion=10 reliefentries=4 reliefconductorwidth=10 reliefairgap=10
PolygonConnect "Thermal relif" [InComponentClass('Thermal relif')] p1: thpad.connectstyle=Relief thpad.reliefconductorwidth=20 thpad.reliefentries=4 thpad.polygonreliefangle="90 Angle" thpad.airgapwidth=7.87 smdpad.connectstyle=Relief smdpad.reliefconductorwidth=15 smdpad.reliefentries=4 smdpad.polygonreliefangle="90 Angle" smdpad.airgapwidth=10 via.connectstyle=Relief via.reliefconductorwidth=10 via.reliefentries=4 via.polygonreliefangle="90 Angle" via.airgapwidth=10
PolygonConnect [All] p2: connectstyle=Direct reliefconductorwidth=10 reliefentries=4 polygonreliefangle="90 Angle" airgapwidth=10
RoomDefinition HSDC106B_EVM_DP83561_64p_USB [InComponentClass('HSDC106B_EVM_DP83561_64p_USB')] p1: confinementstyle=ConfineIn formatcopy=TRUE lockcomponents=FALSE outline -892,-2849.3 1108,-2849.3 1108,-1849.3 -892,-1849.3
RoomDefinition HSDC106B_EVM_DP83561_64p_Straps [InComponentClass('HSDC106B_EVM_DP83561_64p_Straps')] p2: confinementstyle=ConfineIn formatcopy=TRUE lockcomponents=FALSE outline -892,-2849.3 1108,-2849.3 1108,-1849.3 -892,-1849.3
RoomDefinition HSDC106B_EVM_DP83561_64p_PHY [InComponentClass('HSDC106B_EVM_DP83561_64p_PHY')] p3: confinementstyle=ConfineIn formatcopy=TRUE lockcomponents=FALSE outline 8596,-146.3 8814,-146.3 8814,581.7 8596,581.7
RoomDefinition HSDC106B_EVM_DP83561_64p_MSP430 [InComponentClass('HSDC106B_EVM_DP83561_64p_MSP430')] p4: confinementstyle=ConfineIn formatcopy=TRUE lockcomponents=FALSE outline -892,-2849.3 1108,-2849.3 1108,-1849.3 -892,-1849.3
RoomDefinition HSDC106B_EVM_DP83561_64p_MAC_RJ45 [InComponentClass('HSDC106B_EVM_DP83561_64p_MAC_RJ45')] p5: confinementstyle=ConfineIn formatcopy=TRUE lockcomponents=FALSE outline -892,-2849.3 1108,-2849.3 1108,-1849.3 -892,-1849.3
RoomDefinition HSDC106B_EVM_DP83561_64p_Hardware [InComponentClass('HSDC106B_EVM_DP83561_64p_Hardware')] p6: confinementstyle=ConfineIn formatcopy=TRUE lockcomponents=FALSE outline -892,-2849.3 1108,-2849.3 1108,-1849.3 -892,-1849.3
RoomDefinition HSDC106B_EVM_DP83561_64p_EZFET [InComponentClass('HSDC106B_EVM_DP83561_64p_EZFET')] p7: confinementstyle=ConfineIn formatcopy=TRUE lockcomponents=FALSE outline -892,-2849.3 1108,-2849.3 1108,-1849.3 -892,-1849.3
RoomDefinition HSDC106B_EVM_DP83561_64p_Breakout [InComponentClass('HSDC106B_EVM_DP83561_64p_Breakout')] p8: confinementstyle=ConfineIn formatcopy=TRUE lockcomponents=FALSE outline -892,-2849.3 1108,-2849.3 1108,-1849.3 -892,-1849.3
RoomDefinition HSDC106B_EVM_DP83561_64p_PowerSupply [InComponentClass('HSDC106B_EVM_DP83561_64p_PowerSupply')] p9: confinementstyle=ConfineIn formatcopy=TRUE lockcomponents=FALSE outline 3480.72,1840.61 3622.6,1840.61 3622.6,1685.33 3958.6,1685.33 3958.6,1822.61 4109.6,1822.61 4109.6,1973.61 4242.01,1973.61 4242.01,2032.2 4109.6,2032.2 4109.6,2164.61 3977.19,2164.61 3977.19,2346.02 3639.6,2346.02 3639.6,2188.61 3480.72,2188.61
RoutingVias ThermalPadVias [IsVia and InAnyComponent] p1: holewidth=7.87 width=19.68 viastyle="Through Hole" minholewidth=7.87 minwidth=17.87 maxholewidth=12.99 maxwidth=23.62
RoutingVias [All] p2: holewidth=12 width=24 viastyle="Through Hole" minholewidth=7.87 minwidth=17.87 maxholewidth=40 maxwidth=65
SilkToSilkClearance SilkToSilkClearance_Pb-FreeLogo [(HasFootprint('Pb-Free_Overlay_Medium') OR HasFootprint('Pb-Free_Overlay_Small')) vs (HasFootprint('Pb-Free_Overlay_Medium') OR HasFootprint('Pb-Free_Overlay_Small'))] p1: silktosilkclearance=0
SilkToSilkClearance [All] p2: silktosilkclearance=3
SilkToSolderMaskClearance SilkToComponentPadClearance [(IsPad or IsFill or IsRegion) and InAnycomponent] p1: minsilkscreentomaskgap=0 clearancetoexposedcopper=TRUE
SilkToSolderMaskClearance "Silk to Solder Mask Opening" [All] p2: minsilkscreentomaskgap=3 clearancetoexposedcopper=FALSE
SolderMaskExpansion [All] p1: expansion=1.97
Width [All] p1: maxlimit=100 minlimit=5 preferedwidth=10 checkconnectedcopper=TRUE
15 further rules are at their usual default settings.

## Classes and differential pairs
component class HSDC106B_EVM_DP83561_64p_Hardware: FID1 FID2 FID3 FID4 FID5 FID6 FID7 FID8 FID9 FID10 FID11 FID12 FID13 FID14 FID15 FID16 FID17 FID18 H1 H2 H3 H4 H5 H6 H7 H8 Logo1 Logo2 Logo3 Logo4 M1 M2 M3 M4 M5 M6 M7 M8 SH-J1 SH-J2 SH-J3 SH-J4 SH-J5 SH-J6 SH-J7 SH-J8 ZZ1 ZZ2 ZZ3
component class HSDC106B_EVM_DP83561_64p_Breakout: J1 J2 J19 J22 R130 R132 R134 R135 R136 R201 R202 R203 R204 R205 R206 R207
component class HSDC106B_EVM_DP83561_64p_USB: C110 C111 C112 C113 C114 C115 C116 C117 C118 C119 C120 C121 C122 C123 C124 C125 C126 C127 C128 C129 D9 J42 LD7 R174 R175 R176 R177 R178 R179 R180 R181 R182 R183 R184 R185 R186 R187 R188 R189 R190 R191 R192 R193 R194 R195 R196 R197 R198 R199 R200 U13 U14 Y3
pad class J10: J10-MH1 J10-MH2
component class HSDC106B_EVM_DP83561_64p_MSP430: C13 C14 C15 C16 C17 C18 C19 C20 C21 C22 C23 C24 C25 D3 D4 J9 J43 R35 R36 R37 R38 R40 R41 R47 R48 R49 R50 R51 R52 R53 R54 R55 R56 R57 R58 R59 R60 R61 R62 R63 R64 R65 R66 R67 R68 R69 R70 R71 R72 R73 R74 R75 R76 S1 S2 U2 U3 U4 Y2
component class HSDC106B_EVM_DP83561_64p_EZFET: C1 C2 C3 C4 C5 C6 C7 C8 C9 C10 C11 C12 D1 D2 J3 R1 R2 R3 R4 R5 R6 R7 R8 R9 R10 U1 Y1
component class HSDC106B_EVM_DP83561_64p_PHY: C26 C27 C28 C29 C31 C32 C33 C34 C35 C36 C37 C38 C39 C40 C41 C42 C43 C44 C45 C46 C47 C48 C49 C51 J8 J10 J11 J12 J13 J14 J15 J? P1 R77 R78 R79 R80 R81 R82 R83 R84 R85 R86 R87 R88 R89 R90 R91 S3 U5 VPP_TP1 XTAL1
component class HSDC106B_EVM_DP83561_64p_PowerSupply: C50 C52 C53 C55 C56 C57 C58 C59 C60 C61 C62 C63 C64 C65 C66 C67 C68 C70 C71 C73 C74 C75 C76 C78 C80 C81 C83 C84 C85 C86 C87 C88 C91 C92 C93 C94 D5 D6 D7 D8 F1 J16 J17 J18 J20 J21 J23 J24 L1 P2 Q1 Q2 Q3 Q4 R21 R22 R24 R26 R28 R30 R92 R93 R94 R95 R96 R97 R98 R99 R100 R101 R102 R103 R104 R105 R106 R108 R109 R110 R111 R273 R274 R275 R276 R282 R283 U6 U7 U8 U9 U10
component class HSDC106B_EVM_DP83561_64p_MAC_RJ45: C54 C69 C72 C79 C82 C95 C97 C99 C101 C103 C104 C106 C107 C108 C109 J4 J5 J6 J27 R11 R12 R13 R14 R15 R16 R17 R18 R19 R20 R23 R25 R27 R29 R31 R32 R33 R34 R107 R112 R113 R114 R115 R116 R117 R118 R119 R120 R121 R122 R123 R124 R125 R126 R127 R128 R129 R131 R133 R137 R138 R139 R140 R141 R142 R143 R144 R145 R146 R258 R259 R260 R261 R262 R263 R264 R265 T1 TP1 TP2 TP3 TP4 TP5 TP6 TP7 TP8 TP9 TP10 U11 U12
component class HSDC106B_EVM_DP83561_64p_Straps: J28 J29 J30 J31 J32 J33 J34 J35 J36 J37 J38 J39 J40 J41 LD1 LD2 LD3 LD4 LD5 LD6 R147 R148 R149 R150 R151 R152 R153 R154 R155 R156 R157 R158 R159 R160 R161 R162 R163 R164 R165 R166 R167 R168 R169 R170 R171 R172 R173 R229 R230 R231 R236 R237 R?
pad class MH: J2-MP1 J2-MP2 J2-MP3 J2-MP4 M1-1 M3-1 M5-1 M6-1 M7-1 M8-1
differential pair TD_D_mag: +TD_D_mag_P -TD_D_mag_N
differential pair TD_C_mag: +TD_C_mag_P -TD_C_mag_N
differential pair TD_B_mag: +TD_B_mag_P -TD_B_mag_N
differential pair TD_A_mag: +TD_A_mag_P -TD_A_mag_N
differential pair TD_D_x: +TD_D_x_P -TD_D_x_N
differential pair TD_D_RJ: +TD_D_RJ_P -TD_D_RJ_N
differential pair TD_D_cap: +TD_D_cap_P -TD_D_cap_N
differential pair TD_C_x: +TD_C_x_P -TD_C_x_N
differential pair TD_C_RJ: +TD_C_RJ_P -TD_C_RJ_N
differential pair TD_C_cap: +TD_C_cap_P -TD_C_cap_N
differential pair TD_B_x: +TD_B_x_P -TD_B_x_N
differential pair TD_B_RJ: +TD_B_RJ_P -TD_B_RJ_N
differential pair TD_B_cap: +TD_B_cap_P -TD_B_cap_N
differential pair TD_A_x: +TD_A_x_P -TD_A_x_N
differential pair TD_A_RJ: +TD_A_RJ_P -TD_A_RJ_N
differential pair TD_A_cap: +NetC95_1 -TD_A_cap_N
differential pair D0: +D0_P -D0_N
differential pair D1: +D1_P -D1_N
differential pair D2: +D2_P -D2_N
differential pair EZFET_PUD: +EZFET_PUD_P -EZFET_PUD_N
differential pair HUB_D1: +HUB_D1_P -HUB_D1_N
differential pair HUB_D2: +HUB_D2_P -HUB_D2_N
differential pair TARGET_D: +TARGET_D_P -TARGET_D_N
differential pair USB: +USB_P -USB_N

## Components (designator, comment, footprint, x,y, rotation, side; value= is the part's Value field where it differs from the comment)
C1 "CL05B104KO5NNNC" 0402#1 5159.6,4903.61 r0 bottom value=0.1uF
C2 "885012005043" 0402#1 5037.6,5113.61 r180 bottom value=33pF
C3 "885012005043" 0402#1 5037.6,5025.7 r180 top value=33pF
C4 "CL05C360JB5NNNC" 0402#1 5232.1,5255.55 r270 top value=36pF
C5 "CL05C360JB5NNNC" 0402#1 5467.6,5281.61 r90 top value=36pF
C6 "CL10A224KB8NNNC" 0603 5319.6,5077.61 r270 bottom value=0.22uF
C7 "CGA3E3X7R1H474K080AB" 0603 5172.6,4772.61 r90 bottom value=0.47uF
C8 "GRM1555C1H102JA01D" 0402#1 5193,5136.7 r0 top value=1000pF
C9 "CL10A224KB8NNNC" 0603 5378.6,5076.61 r270 bottom value=0.22uF
C10 "TPSD106K035R0125" 7343-31 5000.6,4700.61 r270 bottom value=10uF
C11 "CL05B104KO5NNNC" 0402#1 5060.6,4859.7 r180 top value=0.1uF
C12 "CL05B104KO5NNNC" 0402#1 5465.6,4905.61 r180 bottom value=0.1uF
C13 "GCM155R71H104KE02D" 0402#1 3507.2,4470.61 r270 top value=0.1uF
C14 "GCM155R71H104KE02D" 0402#1 4114.6,4234.61 r270 top value=0.1uF
C15 "CL05C360JB5NNNC" 0402#1 4720.98,4822.61 r0 top value=36pF
C16 "CL05C360JB5NNNC" 0402#1 4721.6,4995.61 r180 bottom value=36pF
C17 "C0603C224Z4VACTU" 0603 4507.6,4881.61 r180 bottom value=0.22uF
C18 "GCM188R71C474KA55D" 0603 4083.6,5180.11 r270 bottom value=0.47uF
C19 "C1608X5R1V475K080AC" 0603 4507.26,4764.18 r0 bottom value=4.7uF
C20 "C0603C224Z4VACTU" 0603 4507.26,4823.24 r180 bottom value=0.22uF
C21 "TPSD106K035R0125" 7343-31 4155.6,5445.61 r0 top value=10uF
C22 "C0402C104K8RACTU" 0402#1 4171.79,5306.61 r0 top value=0.1uF
C23 "C0402C104K8RACTU" 0402#1 4171.79,5259.61 r0 top value=0.1uF
C24 "C0402C104K8RACTU" 0402#1 4223,5259.61 r180 bottom value=0.1uF
C25 "GRM1555C1H102JA01D" 0402#1 5343,4247.61 r0 bottom value=1000pF
C26 "CC0402KRX5R6BB104" FP-CC0402KRX5R6BB104_0402-MFG 3546.6,2065.61 r180 bottom value=100nF
C27 "EMK105BJ105KVHF" 0402#1 3547.6,1971.61 r0 bottom value=1uF
C28 "CC0402KRX5R6BB104" FP-CC0402KRX5R6BB104_0402-MFG 3547.6,2018.61 r180 bottom value=100nF
C29 "CC0402KRX5R6BB104" FP-CC0402KRX5R6BB104_0402-MFG 4081.44,2021.76 r0 bottom value=100nF
C30 "CC0402KRX5R6BB104" FP-CC0402KRX5R6BB104_0402-MFG 4080.6,2068.61 r0 bottom value=100nF
C31 "CC0402KRX5R6BB104" FP-CC0402KRX5R6BB104_0402-MFG 3928.42,2349.36 r180 bottom value=100nF
C32 "CC0402KRX5R6BB104" FP-CC0402KRX5R6BB104_0402-MFG 3928.42,2302.41 r180 bottom value=100nF
C33 "CC0402KRX5R6BB104" FP-CC0402KRX5R6BB104_0402-MFG 3545.6,2113.61 r180 bottom value=100nF
C34 "CC0402KRX5R6BB104" FP-CC0402KRX5R6BB104_0402-MFG 3549.39,1925 r180 bottom value=100nF
C35 "CC0402KRX5R6BB104" FP-CC0402KRX5R6BB104_0402-MFG 3548.6,1880.61 r180 bottom value=100nF
C36 "CC0402KRX5R6BB104" FP-CC0402KRX5R6BB104_0402-MFG 3615.74,2243.98 r90 bottom value=100nF
C37 "CC0402KRX5R6BB104" FP-CC0402KRX5R6BB104_0402-MFG 3663.6,2244.61 r90 bottom value=100nF
C38 "CC0402KRX5R6BB104" FP-CC0402KRX5R6BB104_0402-MFG 3547.24,1786.1 r180 bottom value=100nF
C39 "CC0402KRX5R6BB104" FP-CC0402KRX5R6BB104_0402-MFG 3547.24,1834.92 r180 bottom value=100nF
C40 "CC0402KRX5R6BB104" FP-CC0402KRX5R6BB104_0402-MFG 3773,1712 r0 bottom value=100nF
C41 "CC0402KRX5R6BB104" FP-CC0402KRX5R6BB104_0402-MFG 3773.5,1756 r0 bottom value=100nF
C42 "CC0402KRX5R6BB104" FP-CC0402KRX5R6BB104_0402-MFG 4081.44,1973.7 r0 bottom value=100nF
C43 "CC0402KRX5R6BB104" FP-CC0402KRX5R6BB104_0402-MFG 4081.6,1927.61 r0 bottom value=100nF
C44 "CC0402KRX5R6BB104" FP-CC0402KRX5R6BB104_0402-MFG 3752.6,2242.61 r90 bottom value=100nF
C45 "CC0402KRX5R6BB104" FP-CC0402KRX5R6BB104_0402-MFG 3799.6,2242.61 r90 bottom value=100nF
C46 "885012205067" FP-885012205067_0402-MFG 354.5,769.63 r270 bottom value=10nF
C47 "GRM21BC80G476ME15L" 0805_HV 189.29,667.8 r270 bottom value=47uF
C48 "CMP-0007116-4" 0603 3835.97,1357.3 r270 bottom value=27pF
C49 "CMP-0007116-4" 0603 4178.47,1322.8 r180 bottom value=27pF
C50 "CMP-0009155-2" 1210_280 1000,4917.7 r0 top value=10uF
C51 "GCM1555C1H470FA16D" FP-GCM1555C1H470FA16D_0402-MFG 3426.41,1829.61 r90 top value=47pF
C52 "CMP-0009155-2" 1210_280 995,5080.7 r270 top value=10uF
C53 "0805YD105KAT2A" 0805_HV 996.6,5079.61 r270 bottom value=1uF
C54 "CMP-0006850-4" 0603 1589,1749 r180 bottom value=0.01uF
C55 "CMP-0006324-2" 0402#1 1079.6,5084.61 r270 bottom value=0.01uF
C56 "GCM155R71H104KE02D" 0402#1 701.6,5840.57 r270 top value=0.1uF
C57 "T491D227K006AT" 7343-31 1217.6,5661.61 r270 top value=220uF
C58 "CMP-0006850-4" 0603 1120.1,5758.24 r90 bottom value=0.01uF
C59 "CMP-0006303-2" 0402#1 1099.6,5764.74 r90 top value=100pF
C60 "GMJ316BB7106MLHT" FP-GMJ316BB7106MLHT_1206-MFG 1043.6,5733.95 r90 bottom value=10µF
C61 "CMP-0006850-4" 0603 1043.6,5755.61 r90 top value=0.01uF
C62 "CGA3E1X7R1V105K080AC" 0603 609.1,5913.61 r180 top value=1uF
C63 "EMVE500ADA101MHA0G" CAPSMT_62_HA0 674.6,5505.61 r270 top value=100uF
C64 "CGA6P3X7R1H475K250AB" 1210_280 553.86,5714.61 r270 bottom value=4.7uF
C65 "CGA3E3X7R1H224K080AB" 0603 530.6,5747.61 r270 top value=0.22uF
C66 "CGA6P3X7R1H475K250AB" 1210_280 441.6,5729.61 r270 top value=4.7uF
C67 "CGA3E3X7R1H224K080AB" 0603 640.22,5737.58 r270 bottom value=0.22uF
C68 "CMP-0009155-2" 1210_280 1011,4365.7 r0 top value=10uF
C69 "CMP-0006850-4" 0603 1610.47,1873.53 r180 bottom value=0.01uF
C70 "CMP-0009155-2" 1210_280 962,4529.7 r270 top value=10uF
C71 "0805YD105KAT2A" 0805_HV 963.6,4536.61 r270 bottom value=1uF
C72 "CMP-0006850-4" 0603 1605,2040 r180 bottom value=0.01uF
C73 "CMP-0006324-2" 0402#1 1048,4551.61 r270 bottom value=0.01uF
C74 "CMP-0009154-2" 1210_280 1872.6,4585.65 r90 bottom value=22uF
C75 "CMP-0009154-2" 1210_280 2025.6,5061.61 r90 bottom value=22uF
C76 "CMP-0009154-2" 1210_280 2026.6,5246.61 r270 bottom value=22uF
C77 "CMP-0009154-2" 1210_280 1884.6,3441.61 r90 bottom value=22uF
C78 "CMP-0009155-2" 1210_280 1017,3846.7 r0 top value=10uF
C79 "CMP-0006850-4" 0603 1599,2228 r180 bottom value=0.01uF
C80 "CMP-0009155-2" 1210_280 963,4007.7 r270 top value=10uF
C81 "0805YD105KAT2A" 0805_HV 966.6,4007.61 r270 bottom value=1uF
C82 "C0402C103J5RACTU" 0402#2 537.6,1729.61 r180 top value=0.01uF
C83 "CMP-0006324-2" 0402#1 1046.6,4012.61 r270 bottom value=0.01uF
C84 "CMP-0009154-2" 1210_280 1887.6,3931.61 r90 bottom value=22uF
C85 "GMJ316BB7106MLHT" FP-GMJ316BB7106MLHT_1206-MFG 339.53,3443.24 r270 bottom value=10µF
C86 "GMJ316BB7106MLHT" FP-GMJ316BB7106MLHT_1206-MFG 751,3513.7 r270 bottom value=10µF
C87 "CL10B104KO8NNNC" 0603 833,3486.7 r90 bottom value=0.1uF
C88 "CMP-0006850-4" 0603 832,3487.7 r270 top value=0.01uF
C91 "CMP-0011720-2" 7343-31 294.6,3492.09 r90 top value=100uF
C92 "0805YD105KAT2A" 0805_HV 437.5,3434.7 r270 bottom value=1uF
C93 "CC0805ZRY5V6BB475" 0805_HV 437.5,3434.7 r90 top value=4.7uF
C94 "CMP-0007116-4" 0603 805.6,3308.61 r0 top value=27pF
C95 "CGA2B2X5R1C333K050BA" FP-CGA2B2X5R1C333K050BA_0402-MFG 2152.6,2299.61 r180 bottom value=33nF
C97 "CGA2B2X5R1C333K050BA" FP-CGA2B2X5R1C333K050BA_0402-MFG 2152.6,2252.61 r180 bottom value=33nF
C99 "CGA2B2X5R1C333K050BA" FP-CGA2B2X5R1C333K050BA_0402-MFG 2148.19,2150.98 r180 bottom value=33nF
C101 "CGA2B2X5R1C333K050BA" FP-CGA2B2X5R1C333K050BA_0402-MFG 2148.02,2102.61 r180 bottom value=33nF
C103 "CGA2B2X5R1C333K050BA" FP-CGA2B2X5R1C333K050BA_0402-MFG 2149.6,1974.61 r180 bottom value=33nF
C104 "CGA2B2X5R1C333K050BA" FP-CGA2B2X5R1C333K050BA_0402-MFG 2149.6,1927.61 r180 bottom value=33nF
C106 "CGA2B2X5R1C333K050BA" FP-CGA2B2X5R1C333K050BA_0402-MFG 2148.6,1825.61 r180 bottom value=33nF
C107 "CGA2B2X5R1C333K050BA" FP-CGA2B2X5R1C333K050BA_0402-MFG 2148.6,1778.61 r180 bottom value=33nF
C108 "CMP-0009295-2" 1812_254 382,1502 r90 bottom value=4700pF
C109 "CMP-0009295-2" 1812_254 382,2511.64 r270 bottom value=4700pF
C110 "GRM155R6YA105ME11D" 0402#1 4167.6,5829.61 r180 bottom value=1uF
C111 "GRM188R6YA106MA73D" 0603 4157,5830.7 r180 top value=10uF
C112 "GRM155C81C225KE11D" 0402#1 4161.6,5724.26 r270 top value=2.2uF
C113 "GRM155C81C225KE11D" 0402#1 4161.6,5724.26 r270 bottom value=2.2uF
C114 "GRM188R6YA106MA73D" 0603 4107.6,5712.61 r270 top value=10uF
C115 "06031C471JAT2A" 0603 4263.6,5602.11 r270 top value=470pF
C116 "293D475X9035D2TE3" 7343-31 5145.6,5829.61 r0 bottom value=4.7uF
C117 "C0402C104K8RACTU" 0402#1 5151.04,5964.5 r180 top value=0.1uF
C118 "C1005NP01H220J050BA" 0402#1 5104,5729 r180 top value=22pF
C119 "C1005NP01H220J050BA" 0402#1 5200,5687 r0 top value=22pF
C120 "C1005NP01H220J050BA" 0402#1 4896.6,5552.61 r180 bottom value=22pF
C121 "C1005NP01H220J050BA" 0402#1 4895.98,5596.61 r180 bottom value=22pF
C122 "C0402C100K4GACTU" 0402#1 4782.6,4721.61 r0 top value=10pF
C123 "C0402C100K4GACTU" 0402#1 4782.6,4775.61 r0 top value=10pF
C124 "C1005NP01H220J050BA" 0402#1 4896.41,5468.5 r180 bottom value=22pF
C125 "C1005NP01H220J050BA" 0402#1 4896.41,5509.5 r180 bottom value=22pF
C126 "CL05B104KO5NNNC" 0402#1 5001,5727.7 r180 top value=0.1uF
C127 "C0402C100K4GACTU" 0402#1 4636.24,5471.7 r180 bottom value=10pF
C128 "C0402C100K4GACTU" 0402#1 4637.62,5516.7 r180 bottom value=10pF
C129 "CL05B104KO5NNNC" 0402#1 4925,5700.7 r90 top value=0.1uF
D1 "150060RS75000" WL-SMCW_RED 5180.28,4565.7 r0 top value=Red
D2 "150060VS55040" WL-SMCD-0603 5299.09,4560.04 r180 top value=Green
D3 "HSMF-C165" HSMF-C165_RG 3703.13,5150.01 r180 top value=Rg
D4 "HSMF-C165" HSMF-C165_RG 3704.57,5044.86 r180 top value=Rg
D5 "CMP-0002917-2" QTLP630C_Green 1448.6,4080.61 r90 top value=Green
D6 "CMP-0002917-2" QTLP630C_Green 1458,4587.7 r90 top value=Green
D7 "CMP-0002917-2" QTLP630C_Green 1460,5059.7 r90 top value=Green
D8 "CMP-0002917-2" QTLP630C_Green 1478.6,3501.8 r90 top value=Green
D9 "SSA36" SMA 4802.6,5830.61 r0 bottom value=60V
F1 "F0603E3R00FSTR" 0603 386.05,5816.89 r180 bottom
FID1 "CMP-0077181-1" Fiducial10-30 6108.36,310.06 r90 top
FID2 "CMP-0077181-1" Fiducial10-30 519,6038.7 r90 top
FID3 "CMP-0077181-1" Fiducial10-30 5811,5969 r90 top
FID4 "CMP-0077181-1" Fiducial10-30 7641,1993 r90 top
FID5 "CMP-0077181-1" Fiducial10-30 8445,1981 r90 top
FID6 "CMP-0077181-1" Fiducial10-30 8410,-52 r90 top
FID7 "CMP-0077181-1" Fiducial10-30 7319,-90 r90 top
FID8 "CMP-0077181-1" Fiducial10-30 7373,1972 r90 top
FID9 "CMP-0077181-1" Fiducial10-30 6630.87,1975.12 r90 top
FID10 "CMP-0077181-1" Fiducial10-30 6630.87,1975.12 r90 bottom
FID11 "CMP-0077181-1" Fiducial10-30 7373,1972 r90 bottom
FID12 "CMP-0077181-1" Fiducial10-30 7641,1993 r90 bottom
FID13 "CMP-0077181-1" Fiducial10-30 8445,1981 r90 bottom
FID14 "CMP-0077181-1" Fiducial10-30 8410,-52 r90 bottom
FID15 "CMP-0077181-1" Fiducial10-30 7319,-90 r90 bottom
FID16 "CMP-0077181-1" Fiducial10-30 6105,314 r90 bottom
FID17 "CMP-0077181-1" Fiducial10-30 5811,5970 r90 bottom
FID18 "CMP-0077181-1" Fiducial10-30 517,6034 r90 bottom
H1 "1902C" Keystone_1902C 3025,-10 r180 bottom
H2 "1902C" Keystone_1902C 0,0 r180 bottom
H3 "1902C" Keystone_1902C 0,1348.16 r180 bottom
H4 "1902C" Keystone_1902C 0,5993.7 r180 bottom
H5 "1902C" Keystone_1902C 3025,5993.7 r180 bottom
H6 "1902C" Keystone_1902C 0,2723.83 r180 bottom
H7 "1902C" Keystone_1902C 6190.55,5993.7 r180 bottom
H8 "1902C" Keystone_1902C 6190.55,0 r180 bottom
J1 "ERF8-030-01-L-D-EM2-TR" Samtec_ERF8-030-01-x-D-EM2 8550.21,950 r270 top locked
J2 "TSW-118-07-G-D" TSW-118-07-G-D 7783.6,984.61 r90 top
J3 "TSW-102-07-G-D" TSW-102-07-G-D 5605,5460.7 r270 top
J4 "ERM8-030-01-L-D-EM2-TR" Samtec_ERM8-030-01-L-D-EM2 6390.55,1420 r180 top
J5 "TSW-102-07-G-S" TSW-102-07-G-S 5668.99,839.65 r180 top
J6 "TSW-102-07-G-S" TSW-102-07-G-S 5668.6,2207.61 r180 top
J8 "802-10-012-10-001000" Mill-Max_802-10-012-10-001000 2696,4179 r90 top
J9 "TSW-102-07-G-D" TSW-102-07-G-D 5877.6,4939.61 r270 top
J10 "TSW-102-07-G-S" TSW-102-07-G-S 485.95,711.76 r90 top
J11 "142-0701-851" Emerson_142-0701-851 4716.6,-199.39 r180 top
J12 "TSW-102-07-G-S" TSW-102-07-G-S 4666.6,248.61 r0 top
J13 "142-0701-851" Emerson_142-0701-851 6389.6,3318.11 r270 top
J14 "TSW-102-07-G-S" TSW-102-07-G-S 5801.67,3266.74 r90 top
J15 "CMP-0075407-2" TSW-103-07-G-S 3592.83,3862 r180 top
J16 "PJ-002AH" CUI_PJ-002AH 219.6,5629.61 r180 top
J17 "1729160" Phoenix_1729160 1939,6014.7 r180 top
J18 "TSW-102-07-G-S" TSW-102-07-G-S 295.6,5950.61 r180 top
J19 "ERF8-030-01-L-D-EM2-TR" Samtec_ERF8-030-01-x-D-EM2 7469.7,949.61 r270 top locked
J20 "TSW-102-07-G-S" TSW-102-07-G-S 1702,4641.61 r0 top
J21 "TSW-102-07-G-S" TSW-102-07-G-S 3903.6,6091.61 r180 top
J22 "ERF8-030-01-L-D-EM2-TR" Samtec_ERF8-030-01-x-D-EM2 6469.58,949.61 r90 top locked
J23 "TSW-102-07-G-S" TSW-102-07-G-S 1713,5160.7 r0 top
J24 "TSW-102-07-G-S" TSW-102-07-G-S 1712.6,3505.61 r0 top
J27 "1-406541-1" TEC_1-406541-1 114.53,2003.48 r270 top
J28 "CMP-0075407-2" TSW-103-07-G-S 1368.5,70.98 r180 top
J29 "TSW-102-07-G-S" TSW-102-07-G-S 5668.99,1632.34 r180 top locked
J30 "TSW-102-07-G-S" TSW-102-07-G-S 5668.99,1840.58 r180 top locked
J31 "TSW-102-07-G-S" TSW-102-07-G-S 5668.99,2048.82 r180 top
J32 "TSW-102-07-G-S" TSW-102-07-G-S 5668.99,990 r180 top locked
J33 "CMP-0075407-2" TSW-103-07-G-S 860.5,78.98 r180 top
J34 "TSW-102-07-G-S" TSW-102-07-G-S 5668.99,561.57 r180 top
J35 "TSW-102-07-G-S" TSW-102-07-G-S 5668.99,131.67 r180 top
J36 "TSW-102-07-G-S" TSW-102-07-G-S 5668.99,269.01 r180 top
J37 "TSW-102-07-G-S" TSW-102-07-G-S 5668.99,419.03 r180 top
J38 "CMP-0075407-2" TSW-103-07-G-S 374.5,81.98 r180 top
J39 "TSW-102-07-G-S" TSW-102-07-G-S 5668.99,698.77 r180 top
J40 "TSW-102-07-G-S" TSW-102-07-G-S 5668.99,2521.41 r180 top
J41 "TSW-102-07-G-S" TSW-102-07-G-S 5668.99,2368.28 r180 top
J42 "475890001" Molex_0475890001 5154.83,6193.7 r0 bottom
J43 "CMP-0075407-2" TSW-103-07-G-S 4199.6,3876.61 r180 top
L1 "SRP5030T-100M" SRP5030T 865.18,5801.61 r0 top value=10uH
LD1 "CMP-0002917-2" QTLP630C_Green 1268,-44 r180 top value=Green
LD2 "CMP-0002917-2" QTLP630C_Green 1450,-40 r0 top value=Green
LD3 "CMP-0002917-2" QTLP630C_Green 763.89,-34.95 r180 top value=Green
LD4 "CMP-0002917-2" QTLP630C_Green 945.5,-35 r0 top value=Green
LD5 "CMP-0002917-2" QTLP630C_Green 280,-35 r180 top value=Green
LD6 "CMP-0002917-2" QTLP630C_Green 465,-35 r180 top value=Green
LD7 "QTLP630C4TR" QTLP630C_Green 3987.6,5682.7 r0 top value=Green
Logo1 "CE Mark" CE_Mark_5mm 587,1072 r0 top
Logo2 "Texas Instruments" TI_Stacked_Overlay_Small 5699,3956 r0 top
Logo3 "FCC disclaimer" FCC_disclaimer 12309,361.7 r90 top
Logo4 "WEEE logo" WEEE_Minimum 5913,4412 r0 top
M1 "NY PMS 440 0025 PH" "NY PMS 440 0025 PH" 6190.55,5993.7 r0 top locked
M2 "NY PMS 440 0025 PH" "NY PMS 440 0025 PH" 6190.55,0 r0 top locked
M3 "NY PMS 440 0025 PH" "NY PMS 440 0025 PH" 0,5993.7 r0 top locked
M4 "NY PMS 440 0025 PH" "NY PMS 440 0025 PH" 0,0 r0 top locked
M5 "NY PMS 440 0025 PH" "NY PMS 440 0025 PH" 3025,5993.7 r0 top locked
M6 "NY PMS 440 0025 PH" "NY PMS 440 0025 PH" 3025,-10 r0 top locked
M7 "NY PMS 440 0025 PH" "NY PMS 440 0025 PH" 0,2723.83 r0 top locked
M8 "NY PMS 440 0025 PH" "NY PMS 440 0025 PH" 0,1348.16 r0 top locked
P1 "CMP-0075408-3" TSW-104-07-G-D 1368.49,884.31 r180 top
P2 "TSW-103-07-G-D" TSW-103-07-G-D 1713.83,3991.7 r270 top
Q1 "DNBT8105-7" SOT-23 1370,4075.7 r0 bottom value="60 V"
Q2 "DNBT8105-7" SOT-23 1374.4,4582.1 r0 bottom value="60 V"
Q3 "DNBT8105-7" SOT-23 1379,5054.7 r0 bottom value="60 V"
Q4 "DNBT8105-7" SOT-23 1373,3519.7 r0 bottom value="60 V"
R1 "CRCW0402470RJNED" 0402#1 5216,4643.08 r90 top value=470
R2 "CRCW0402470RJNED" 0402#1 5264,4643.08 r90 top value=470
R3 "CRCW0402240KJNED" 0402#1 5037.6,5072.61 r180 top value=240k
R4 "CRCW0402220KJNED" 0402#1 5037.6,5025.7 r180 bottom value=220k
R5 "CRCW0402150KJNED" 0402#1 5037.6,5072.61 r0 bottom value=150k
R6 "CRCW0402220KJNED" 0402#1 5037.6,4982.7 r0 bottom value=220k
R7 "RC0402JR-070RL" 0402#1 5232.1,5255.55 r90 bottom value=0
R8 "CRCW040247K0JNED" 0402#1 5096,5136.7 r180 top value=47k
R9 "RC0402JR-070RL" 0402#1 5640.6,4974.7 r0 bottom value=0
R10 "RC0402JR-070RL" 0402#1 5640.6,4932.61 r0 bottom value=0
R11 "ERJ-2GE0R00X" 0402#1 3971.39,2876.53 r90 top value=0
R12 "ERJ-2GE0R00X" 0402#1 4100.51,2882.61 r90 top value=0
R13 "ERJ-2GE0R00X" 0402#1 5830.98,838.61 r0 bottom value=0
R14 "ERJ-2GE0R00X" 0402#1 5821.6,1841.61 r0 top value=0
R15 "ERJ-2GE0R00X" 0402#1 5824.6,1631.61 r0 top value=0
R16 "ERJ-2GE0R00X" 0402#1 5824.97,1421.22 r0 top value=0
R17 "ERJ-2GE0R00X" 0402#1 5822.6,1204.24 r0 top value=0
R18 "ERJ-2GE0R00X" 0402#1 5832.24,990 r0 top value=0
R19 "ERJ-2GE0R00X" 0402#1 5824.97,2048.82 r0 top value=0
R20 "ERJ-2GE0R00X" 0402#1 5832.24,942.76 r0 top value=0
R21 "CMP-0025885-5" 0603 819.6,4783.61 r0 top value=0
R22 "CMP-0025885-5" 0603 822.6,4230.61 r0 top value=0
R23 "ERJ-2GE0R00X" 0402#1 5824.97,1793.33 r0 top value=0
R24 "CMP-0025885-5" 0603 823.6,3708.61 r0 top value=0
R25 "ERJ-2GE0R00X" 0402#1 5824.97,1585.09 r0 top value=0
R26 "CMP-0025885-5" 0603 508.6,3327.1 r90 top value=0
R27 "ERJ-2GE0R00X" 0402#1 5824.97,1373.98 r0 top value=0
R28 "RC0603FR-071K87L" 0603 805.6,3370.15 r0 top value=1.87k
R29 "ERJ-2GE0R00X" 0402#1 5822.6,1157 r0 top value=0
R30 "CRCW06034K99FKEAC" 0603 805.6,3370.15 r180 bottom value=4.99k
R31 "ERJ-2GE0R00X" 0402#1 5824.97,2001.57 r0 top value=0
R32 "ERJ-2GE0R00X" 0402#1 5834.22,2216.48 r0 bottom value=0
R33 "ERJ-2GE0R00X" 0402#1 5826.6,2361.61 r0 bottom value=0
R34 "ERJ-2GE0R00X" 0402#1 3822,2426.17 r0 bottom value=0
R35 "CRCW0402374KFKED" 0402#1 3530.65,4396.32 r0 top value=374k
R36 "ERJ-2RKF1004X" 0402#1 3527.6,4346.61 r180 top value=1.00Meg
R37 "CRCW0402374KFKED" 0402#1 4140.6,4156.61 r0 top value=374k
R38 "ERJ-2RKF1004X" 0402#1 4140.6,4113.61 r180 top value=1.00Meg
R40 "CRCW0603200KJNEA" 0603 3448.6,4470.61 r270 top value=200k
R41 "CRCW0603200KJNEA" 0603 4055.6,4225.61 r270 top value=200k
R42 "ERJ-2RKF2201X" 0402#1 3156,4029 r0 bottom value=2.20k
R43 "ERJ-2RKF2201X" 0402#1 3158,4130 r0 bottom value=2.20k
R44 "ERJ-2RKF2201X" 0402#1 3157,4230 r0 bottom value=2.20k
R47 "CRCW04022K20FKED" 0402#1 3611.45,4346.8 r270 top value=2.20k
R48 "CRCW04022K20FKED" 0402#1 4230.1,4118.11 r270 top value=2.20k
R49 "CRCW040210K0JNED" 0402#1 4721.6,5041.8 r0 top value=10k
R50 "CRCW040210K0JNED" 0402#1 4721.6,5090.07 r0 top value=10k
R51 "CRCW04022K20FKED" 0402#1 3663.64,4347.8 r270 top value=2.20k
R52 "CRCW040210K0JNED" 0402#1 4721.6,5138.34 r0 top value=10k
R53 "CRCW040210K0JNED" 0402#1 4721.6,5186.61 r0 top value=10k
R54 "ERJ-2GE0R00X" 0402#1 4169.71,4238.67 r90 bottom value=0
R55 "ERJ-2GE0R00X" 0402#1 3611.45,4348.76 r90 bottom value=0
R56 "ERJ-2GE0R00X" 0402#1 4249.6,4242.98 r90 top value=0
R57 "ERJ-2GE0R00X" 0402#1 3663.64,4347.8 r90 bottom value=0
R58 "ERJ-2GE0R00X" 0402#1 4721.6,5041.8 r180 bottom value=0
R59 "CRCW040210K0JNED" 0402#1 4721.6,5090.07 r180 bottom value=10k
R60 "CRCW040210K0JNED" 0402#1 4721.6,5138.34 r180 bottom value=10k
R61 "CRCW040210K0JNED" 0402#1 4721.6,5186.61 r180 bottom value=10k
R62 "CRCW04022K20FKED" 0402#1 4397.6,5458.61 r90 bottom value=2.20k
R63 "CRCW04022K20FKED" 0402#1 4441.6,5458.61 r90 bottom value=2.20k
R64 "CRCW04022K20FKED" 0402#1 4484.6,5458.61 r90 bottom value=2.20k
R65 "CRCW04022K20FKED" 0402#1 4528.6,5458.61 r90 bottom value=2.20k
R66 "CRCW04022K20FKED" 0402#1 4112.22,4506.61 r180 top value=2.20k
R67 "CRCW04022K20FKED" 0402#1 4214.98,4506.61 r0 top value=2.20k
R68 "CRCW04020000Z0ED" 0402#1 4721.6,4995.61 r180 top value=0
R69 "RC0201JR-07470RL" 0201 3734.05,5161.57 r0 bottom value=470
R70 "RC0201JR-07470RL" 0201 3734.05,5129.86 r0 bottom value=470
R71 "RC0201JR-07470RL" 0201 3734.1,5060.61 r0 bottom value=470
R72 "RC0201JR-07470RL" 0201 3734.1,5027.14 r0 bottom value=470
R73 "CRCW04021K40FKED" 0402#1 4648,4699.7 r90 top value=1.40k
R74 "CRCW04021M00FKED" 0402#1 4599.6,4639.61 r270 top value=1.00Meg
R75 "CRCW040247K0JNED" 0402#1 5343,4295.61 r180 bottom value=47k
R76 "CRCW04020000Z0ED" 0402#1 4192.85,5164.73 r0 bottom value=0
R77 "CMP-0025885-5" 0603 3906.6,1493.61 r90 bottom value=0
R78 "CMP-0025885-5" 0603 4178.47,1383.8 r180 bottom value=0
R79 "CRCW0402470RJNED" 0402#1 355.45,674.23 r90 bottom value=470
R80 "ERJ-2GEJ101X" 0402#1 187.29,798.8 r90 bottom value=100
R81 "CMP-0026727-1" 0402#1 4030.97,1255.8 r0 bottom value=1.00Meg
R82 "CMP-0025885-5" 0603 4177.6,1444.98 r180 bottom value=0
R83 "RMCF0402FT10K0" 0402#1 3426.41,1829.61 r270 bottom value=10.0k
R84 "CMP-0025885-5" 0603 4177.6,1506.61 r180 bottom value=0
R85 "CMP-0026890-5" 0402#1 4273.1,4117.61 r90 top value=2.2k
R86 "CMP-0026890-5" 0402#1 1518.49,740.69 r90 bottom value=2.2k
R87 "CMP-0026890-5" 0402#1 3388.6,3862 r180 bottom value=2.2k
R88 "CMP-0026890-5" 0402#1 1318.49,740.69 r90 bottom value=2.2k
R89 "CMP-0026890-5" 0402#1 1218.49,740.69 r90 bottom value=2.2k
R90 "CMP-0023246-5" 0603 3813.6,3861.61 r180 bottom value=6.04k
R91 "CMP-0022558-4" 0603 1420.6,729.61 r90 bottom value=6.04k
R92 "RC0603FR-071K2L" 0603 918,5252.7 r0 bottom value=1.20k
R93 "CRCW0603100KFKEA" 0603 931.6,5646.61 r0 top value=100k
R94 "CMP-0023374-3" 0603 822,5286.2 r270 bottom value=2.40k
R95 "CRCW060324K9FKEA" 0603 931.6,5646.61 r180 bottom value=24.9k
R96 "RC0603FR-072K55L" 0603 904,4705.7 r0 bottom value=2.55k
R97 "CMP-0025885-5" 0603 1899.6,5124.61 r0 bottom value=0
R98 "CMP-0023374-3" 0603 801,4741.2 r270 bottom value=2.40k
R99 "CMP-0025885-5" 0603 1900,5188.7 r0 bottom value=0
R100 "CMP-0022451-4" 0603 943,4162.7 r0 bottom value=4.22k
R101 "CMP-0023374-3" 0603 829,4195.7 r270 bottom value=2.40k
R102 "CMP-0026934-3" 0402#1 1465.6,4071.61 r90 bottom value=470
R103 "CMP-0026934-3" 0402#1 1471.6,4583.61 r90 bottom value=470
R104 "CMP-0026934-3" 0402#1 1477.6,5053.61 r90 bottom value=470
R105 "CMP-0026934-3" 0402#1 1478.6,3513.61 r90 bottom value=470
R106 "CMP-0022746-5" 0603 634,3505.7 r180 bottom value=10.0k
R107 "CMP-0026544-2" 0402#1 704.6,1737.61 r0 top value=75.0
R108 "CRCW04022K49FKED" 0402#1 1274.6,4072.61 r270 bottom value=2.49k
R109 "CRCW04022K49FKED" 0402#1 1278.6,4580.61 r270 bottom value=2.49k
R110 "CRCW04022K49FKED" 0402#1 1283.6,5054.61 r270 bottom value=2.49k
R111 "CRCW04022K49FKED" 0402#1 1274.6,3519.61 r270 bottom value=2.49k
R112 "ERJ-2GE0R00X" 0402#1 703,1795 r0 top value=0
R113 "ERJ-2GE0R00X" 0402#1 703,1839 r0 top value=0
R114 "CMP-0026544-2" 0402#1 701.38,1893.61 r0 top value=75.0
R115 "ERJ-2GE0R00X" 0402#1 701,1944 r0 top value=0
R116 "ERJ-2GE0R00X" 0402#1 701,1990 r0 top value=0
R117 "CMP-0026544-2" 0402#1 701.38,2041.7 r0 top value=75.0
R118 "ERJ-2GE0R00X" 0402#1 701,2092 r0 top value=0
R119 "ERJ-2GE0R00X" 0402#1 2586.65,2231.7 r0 top value=0
R120 "ERJ-2GE0R00X" 0402#1 2586.65,2231.7 r0 bottom value=0
R121 "ERJ-2GE0R00X" 0402#1 700.81,2138.61 r0 top value=0
R122 "ERJ-2GE0R00X" 0402#1 2586.65,2189.7 r0 top value=0
R123 "CMP-0026544-2" 0402#1 700,2192.09 r0 top value=75.0
R124 "ERJ-2GE0R00X" 0402#1 2586.65,2189.7 r0 bottom value=0
R125 "ERJ-2GE0R00X" 0402#1 700,2243 r0 top value=0
R126 "ERJ-2GE0R00X" 0402#1 1643,1806 r180 bottom value=0
R127 "ERJ-2GE0R00X" 0402#1 2586.65,2114.51 r0 top value=0
R128 "ERJ-2GE0R00X" 0402#1 699.6,2290.61 r0 top value=0
R129 "ERJ-2GE0R00X" 0402#1 2586.65,2114.51 r0 bottom value=0
R130 "ERJ-2GE0R00X" 0402#1 7080.6,636.61 r0 bottom value=0
R131 "ERJ-2GE0R00X" 0402#1 2586.65,2072.7 r0 top value=0
R132 "ERJ-2GE0R00X" 0402#1 7080.6,685.15 r0 bottom value=0
R133 "ERJ-2GE0R00X" 0402#1 2586.65,2072.7 r0 bottom value=0
R134 "ERJ-2GE0R00X" 0402#1 7080.6,733.7 r0 bottom value=0
R135 "ERJ-2GE0R00X" 0402#1 7080.6,782.24 r0 bottom value=0
R136 "ERJ-2GE0R00X" 0402#1 7080.6,830.79 r0 bottom value=0
R137 "ERJ-2GE0R00X" 0402#1 2586.65,1998.51 r0 top value=0
R138 "ERJ-2GE0R00X" 0402#1 2586.65,1998.51 r0 bottom value=0
R139 "ERJ-2GE0R00X" 0402#1 2586.65,1958.51 r0 top value=0
R140 "ERJ-2GE0R00X" 0402#1 2586.65,1958.51 r0 bottom value=0
R141 "ERJ-2GE0R00X" 0402#1 2586.65,1883.51 r0 top value=0
R142 "ERJ-2GE0R00X" 0402#1 2586.65,1883.51 r0 bottom value=0
R143 "ERJ-2GE0R00X" 0402#1 2586.65,1842.51 r0 top value=0
R144 "ERJ-2GE0R00X" 0402#1 2586.65,1842.51 r0 bottom value=0
R145 "CMP-0026727-1" 0402#1 482,1508 r270 bottom value=1.00Meg
R146 "CMP-0026727-1" 0402#1 482,2484 r90 bottom value=1.00Meg
R147 "CRCW0402470RJNED" 0402#1 1320.5,-43.4 r90 bottom value=470
R148 "CRCW04022K49FKED" 0402#1 1244.5,-43.4 r270 bottom value=2.49k
R149 "CRCW0402470RJNED" 0402#1 1421.5,-43.4 r90 bottom value=470
R150 "CRCW04022K49FKED" 0402#1 1500,-45 r90 bottom value=2.49k
R151 "CRCW04022K49FKED" 0402#1 5514.94,1631.93 r180 bottom value=2.49k
R152 "CRCW04026K04FKED" 0402#1 5671.47,1205.42 r180 top value=6.04k
R153 "CRCW04022K49FKED" 0402#1 5518.64,1840.17 r180 bottom value=2.49k
R154 "CRCW04022K49FKED" 0402#1 5671.47,1205.42 r0 bottom value=2.49k
R155 "CRCW04026K04FKED" 0402#1 5672.01,1421.22 r180 top value=6.04k
R156 "CRCW04022K49FKED" 0402#1 5514.94,2048.41 r180 bottom value=2.49k
R157 "CRCW0402470RJNED" 0402#1 812.5,-33.4 r90 bottom value=470
R158 "CRCW04022K49FKED" 0402#1 5672.01,1421.22 r0 bottom value=2.49k
R159 "CRCW04022K49FKED" 0402#1 729.5,-33.4 r270 bottom value=2.49k
R160 "CRCW04022K49FKED" 0402#1 5514.94,989.59 r180 bottom value=2.49k
R161 "CRCW0402470RJNED" 0402#1 904,-33.4 r90 bottom value=470
R162 "CRCW04022K49FKED" 0402#1 986,-33.4 r90 bottom value=2.49k
R163 "CRCW04022K49FKED" 0402#1 5514.94,561.16 r180 bottom value=2.49k
R164 "CRCW04022K49FKED" 0402#1 5513.6,132.61 r180 bottom value=2.49k
R165 "CRCW04022K49FKED" 0402#1 5514.94,268.61 r180 bottom value=2.49k
R166 "CRCW0402470RJNED" 0402#1 326.49,-33.43 r90 bottom value=470
R167 "CRCW04022K49FKED" 0402#1 5514.94,418.62 r180 bottom value=2.49k
R168 "CRCW04022K49FKED" 0402#1 239.5,-33.4 r270 bottom value=2.49k
R169 "CRCW04022K49FKED" 0402#1 5514.94,698.36 r180 bottom value=2.49k
R170 "CRCW0402470RJNED" 0402#1 509.5,-33.4 r90 bottom value=470
R171 "CRCW04022K49FKED" 0402#1 420.5,-33.4 r90 bottom value=2.49k
R172 "CRCW04022K49FKED" 0402#1 5514.94,2521 r180 bottom value=2.49k
R173 "CRCW04022K49FKED" 0402#1 5514.94,2367.87 r180 bottom value=2.49k
R174 "CRCW0402100KDHEDP" 0402#1 4210,5725.04 r90 top value=100k
R175 "CRCW0402470RJNED" 0402#1 3987.6,5742.61 r0 top value=470
R176 "CRCW0402165KFKED" 0402#1 4210,5612.94 r90 top value=165k
R177 "CRCW040233R0JNED" 0402#1 4944,6027.7 r270 bottom value=33
R178 "CRCW04021K50FKED" 0402#1 5200,5729 r0 top value=1.50k
R179 "CRCW040210K0JNED" 0402#1 4989,5357.7 r270 top value=10k
R180 "CRCW040227R0JNED" 0402#1 4648,4795.7 r90 top value=27
R181 "CRCW040222R0JNED" 0402#1 5122,5825 r270 top value=22
R182 "CRCW040222R0JNED" 0402#1 5163.41,5824.5 r270 top value=22
R183 "CRCW040227R0JNED" 0402#1 4705,4699.7 r270 top value=27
